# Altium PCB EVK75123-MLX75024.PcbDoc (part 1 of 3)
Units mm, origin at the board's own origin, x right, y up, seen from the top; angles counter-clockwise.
Board outline 80 x 50 mm, 8 copper layers (Top Layer, GND_T, Signal Layer 1, Vcc1, Vcc2, Signal Layer 2, GND_B, Bottom Layer), stack 1.548 mm thick; 222 components, 135 nets, 746 pads, 778 vias.
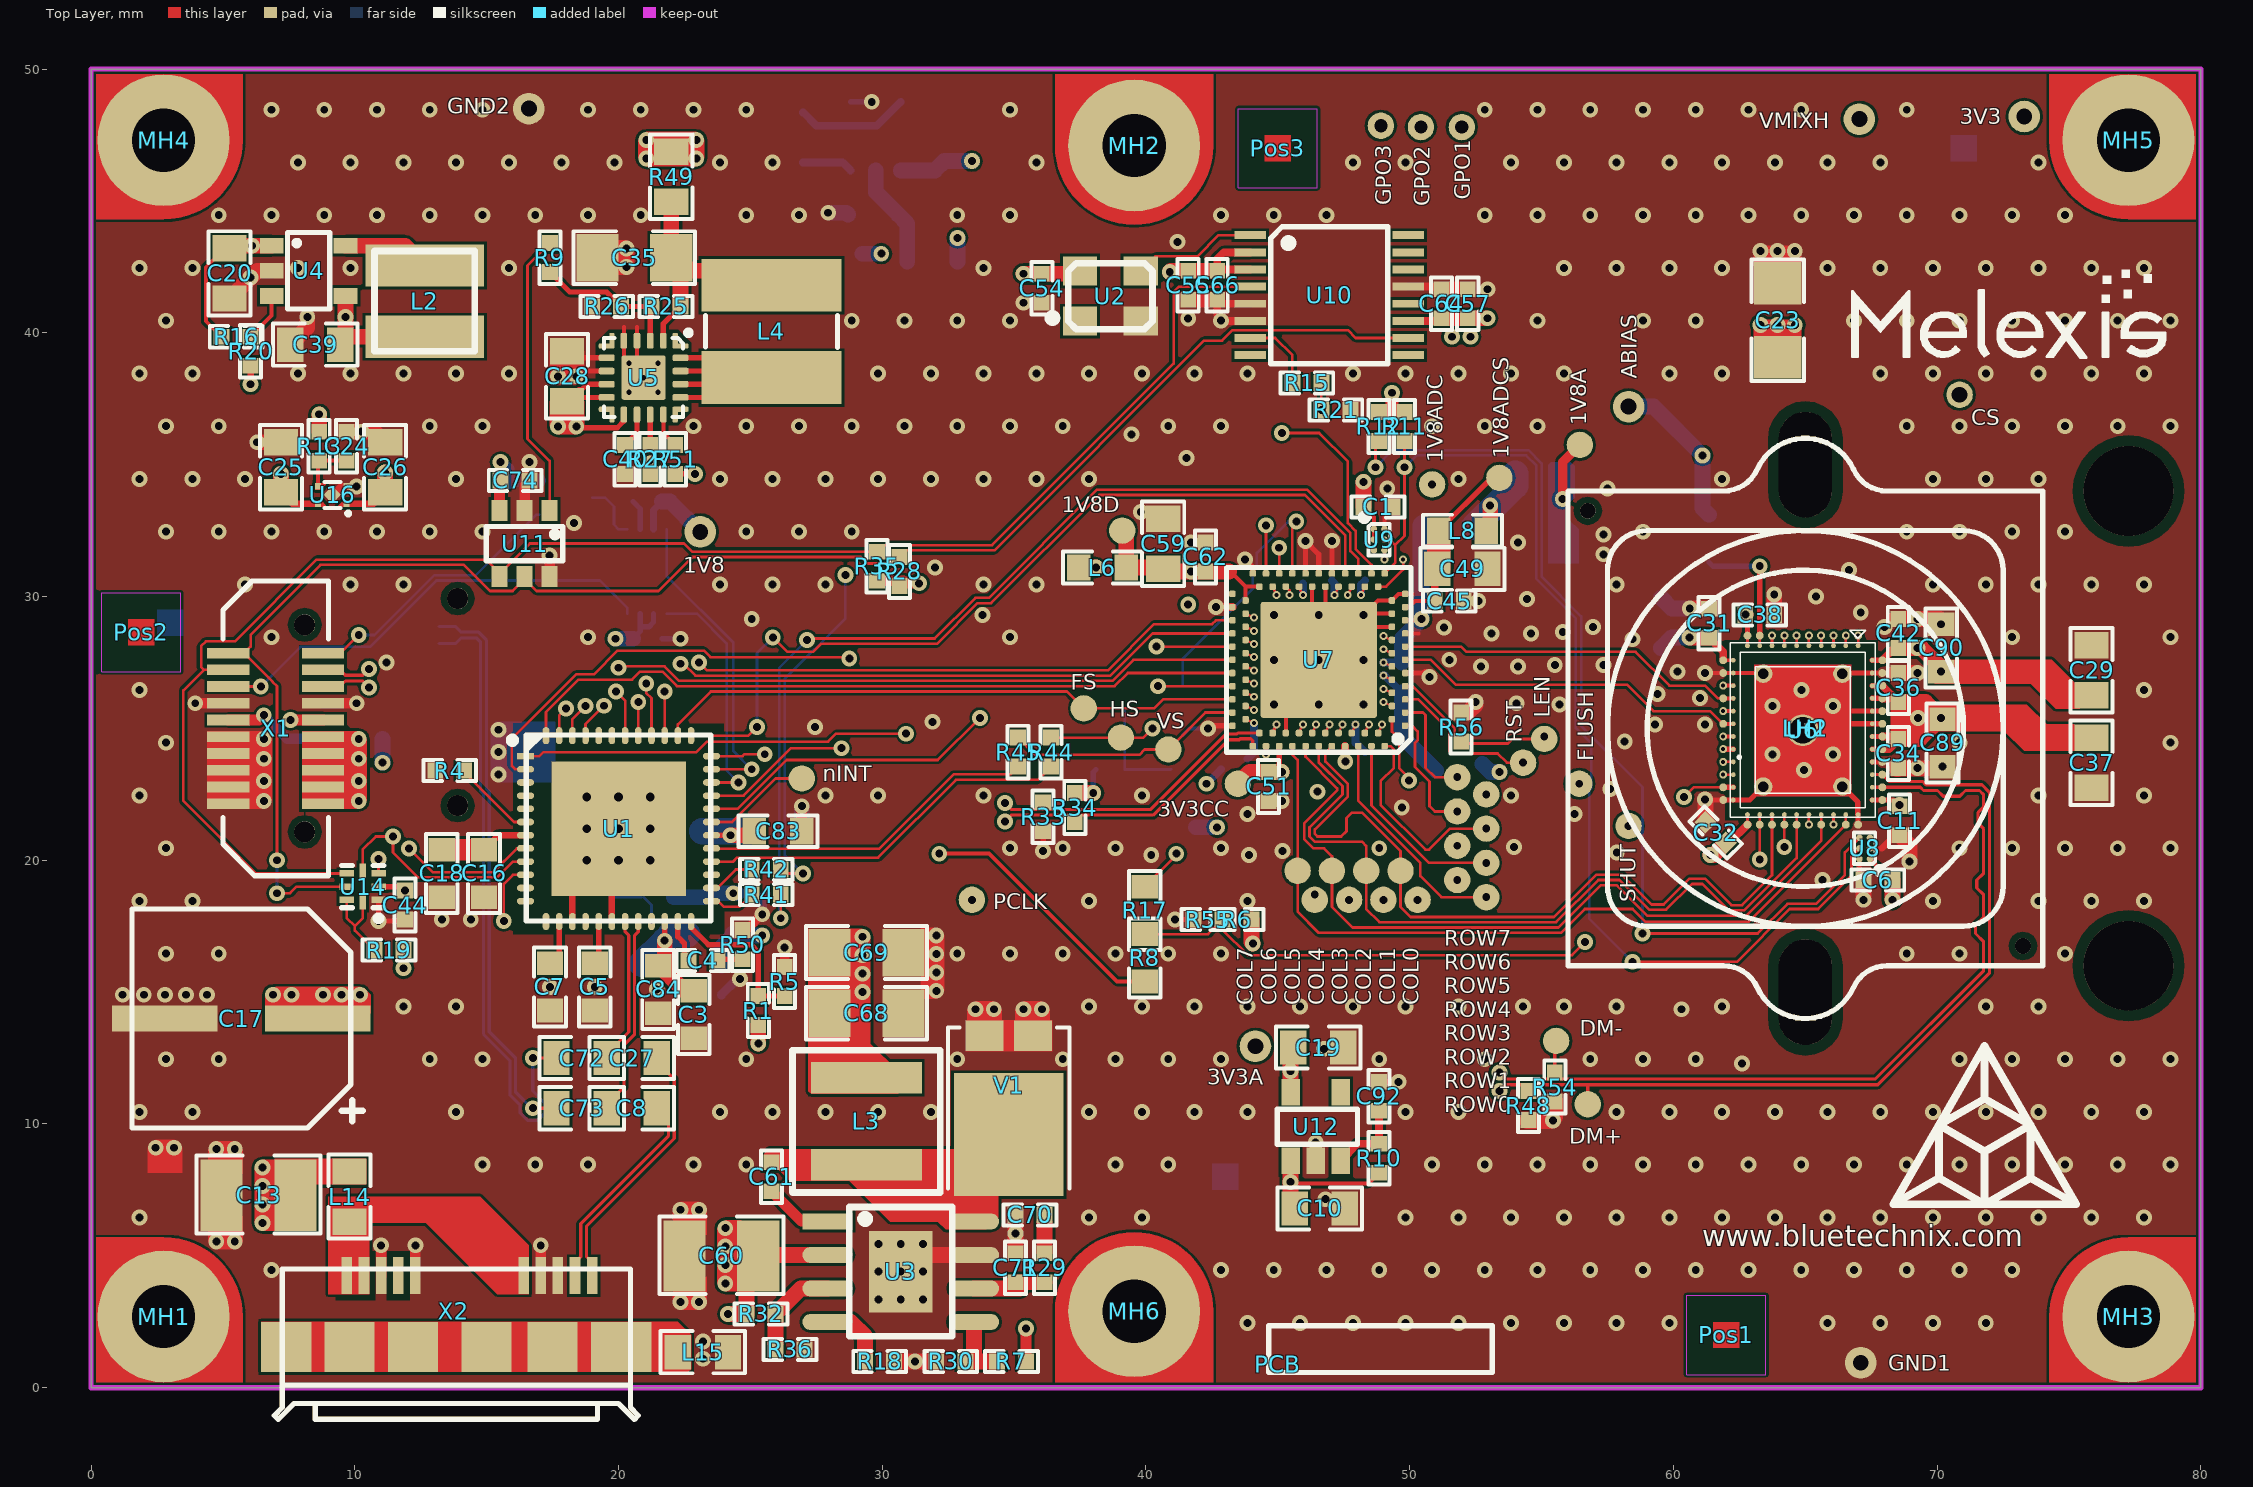
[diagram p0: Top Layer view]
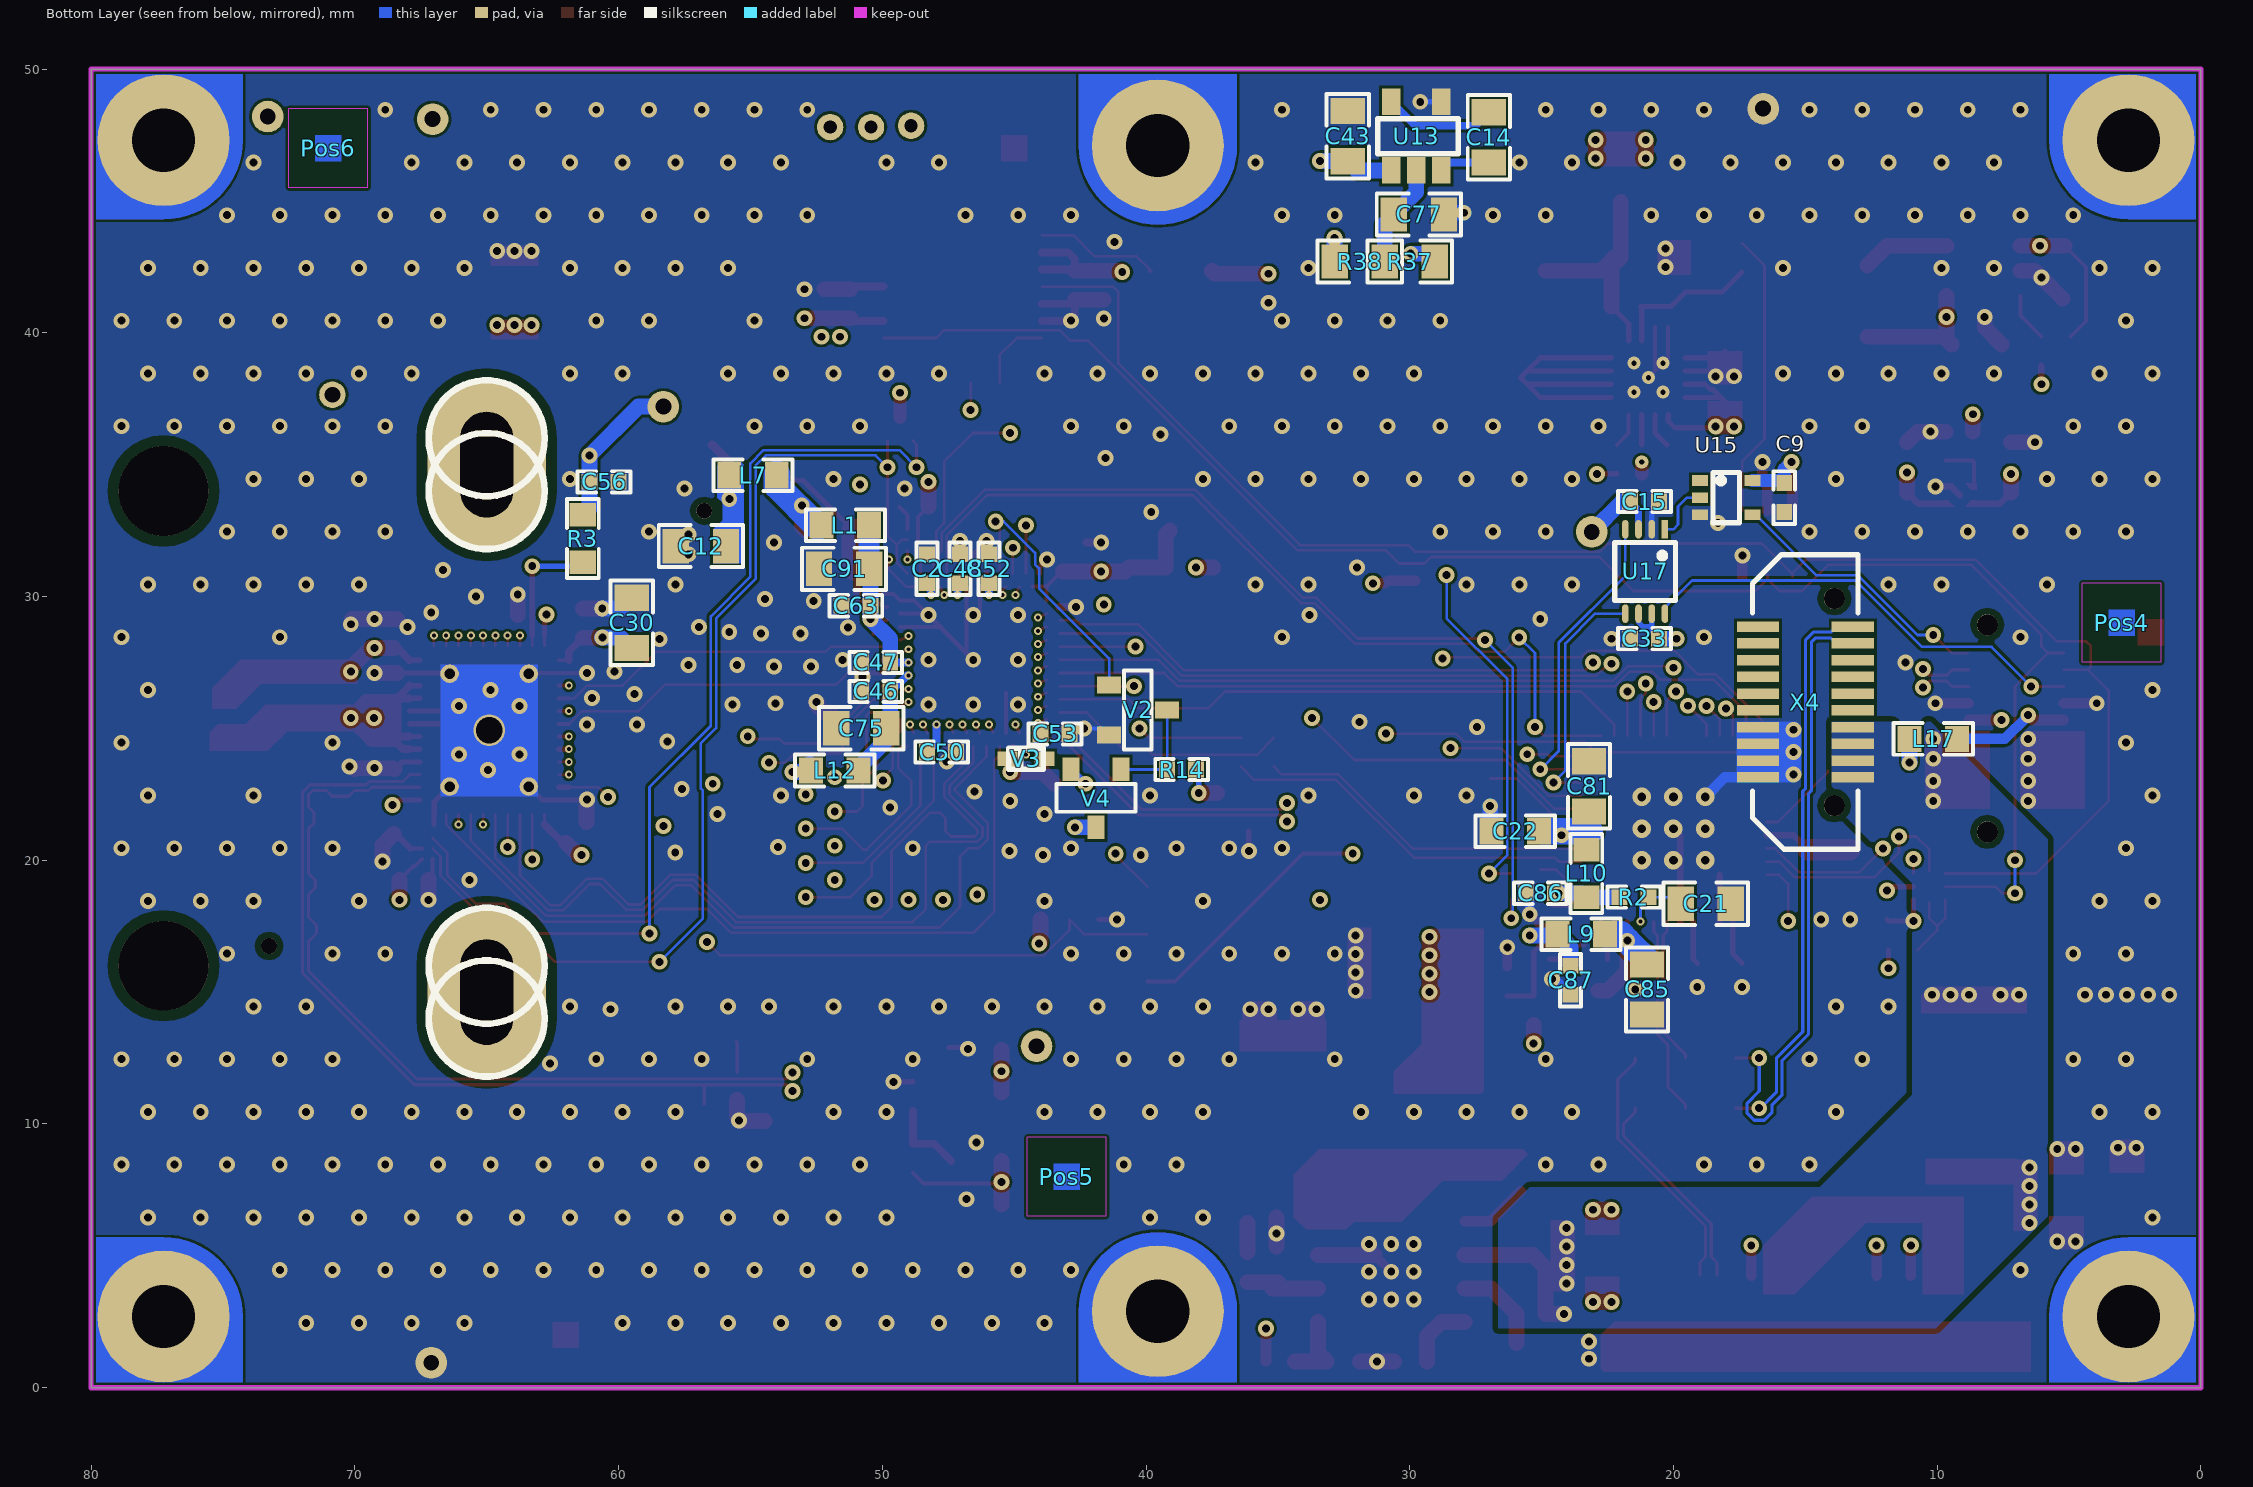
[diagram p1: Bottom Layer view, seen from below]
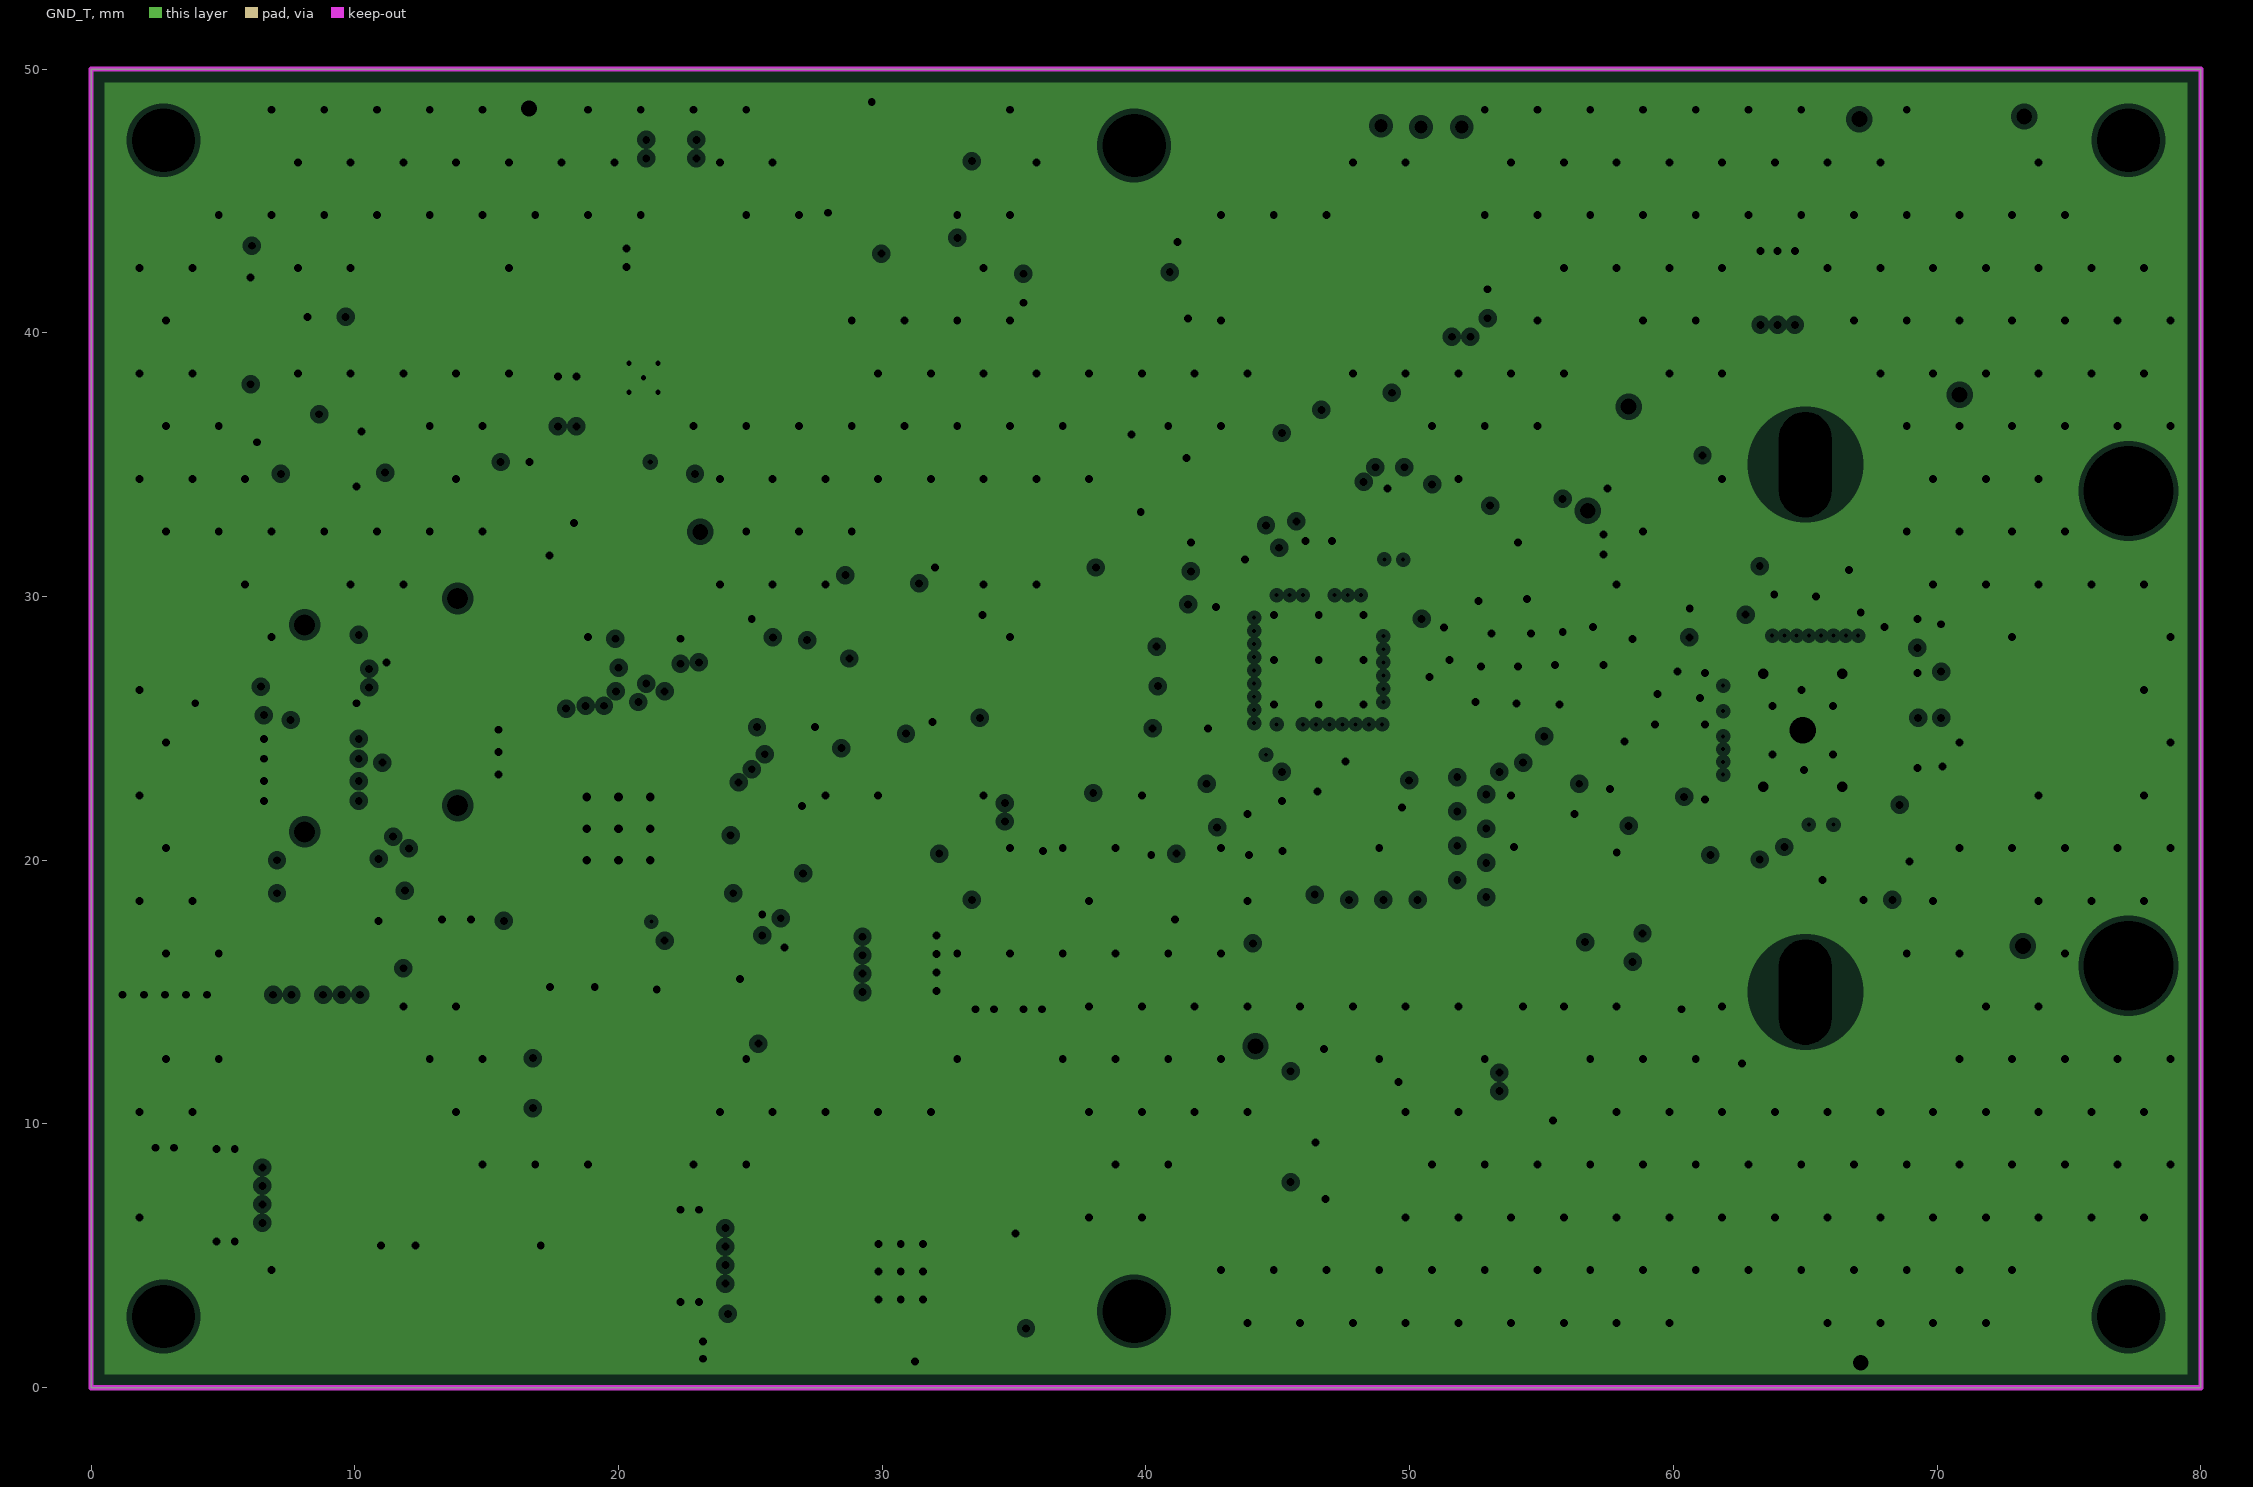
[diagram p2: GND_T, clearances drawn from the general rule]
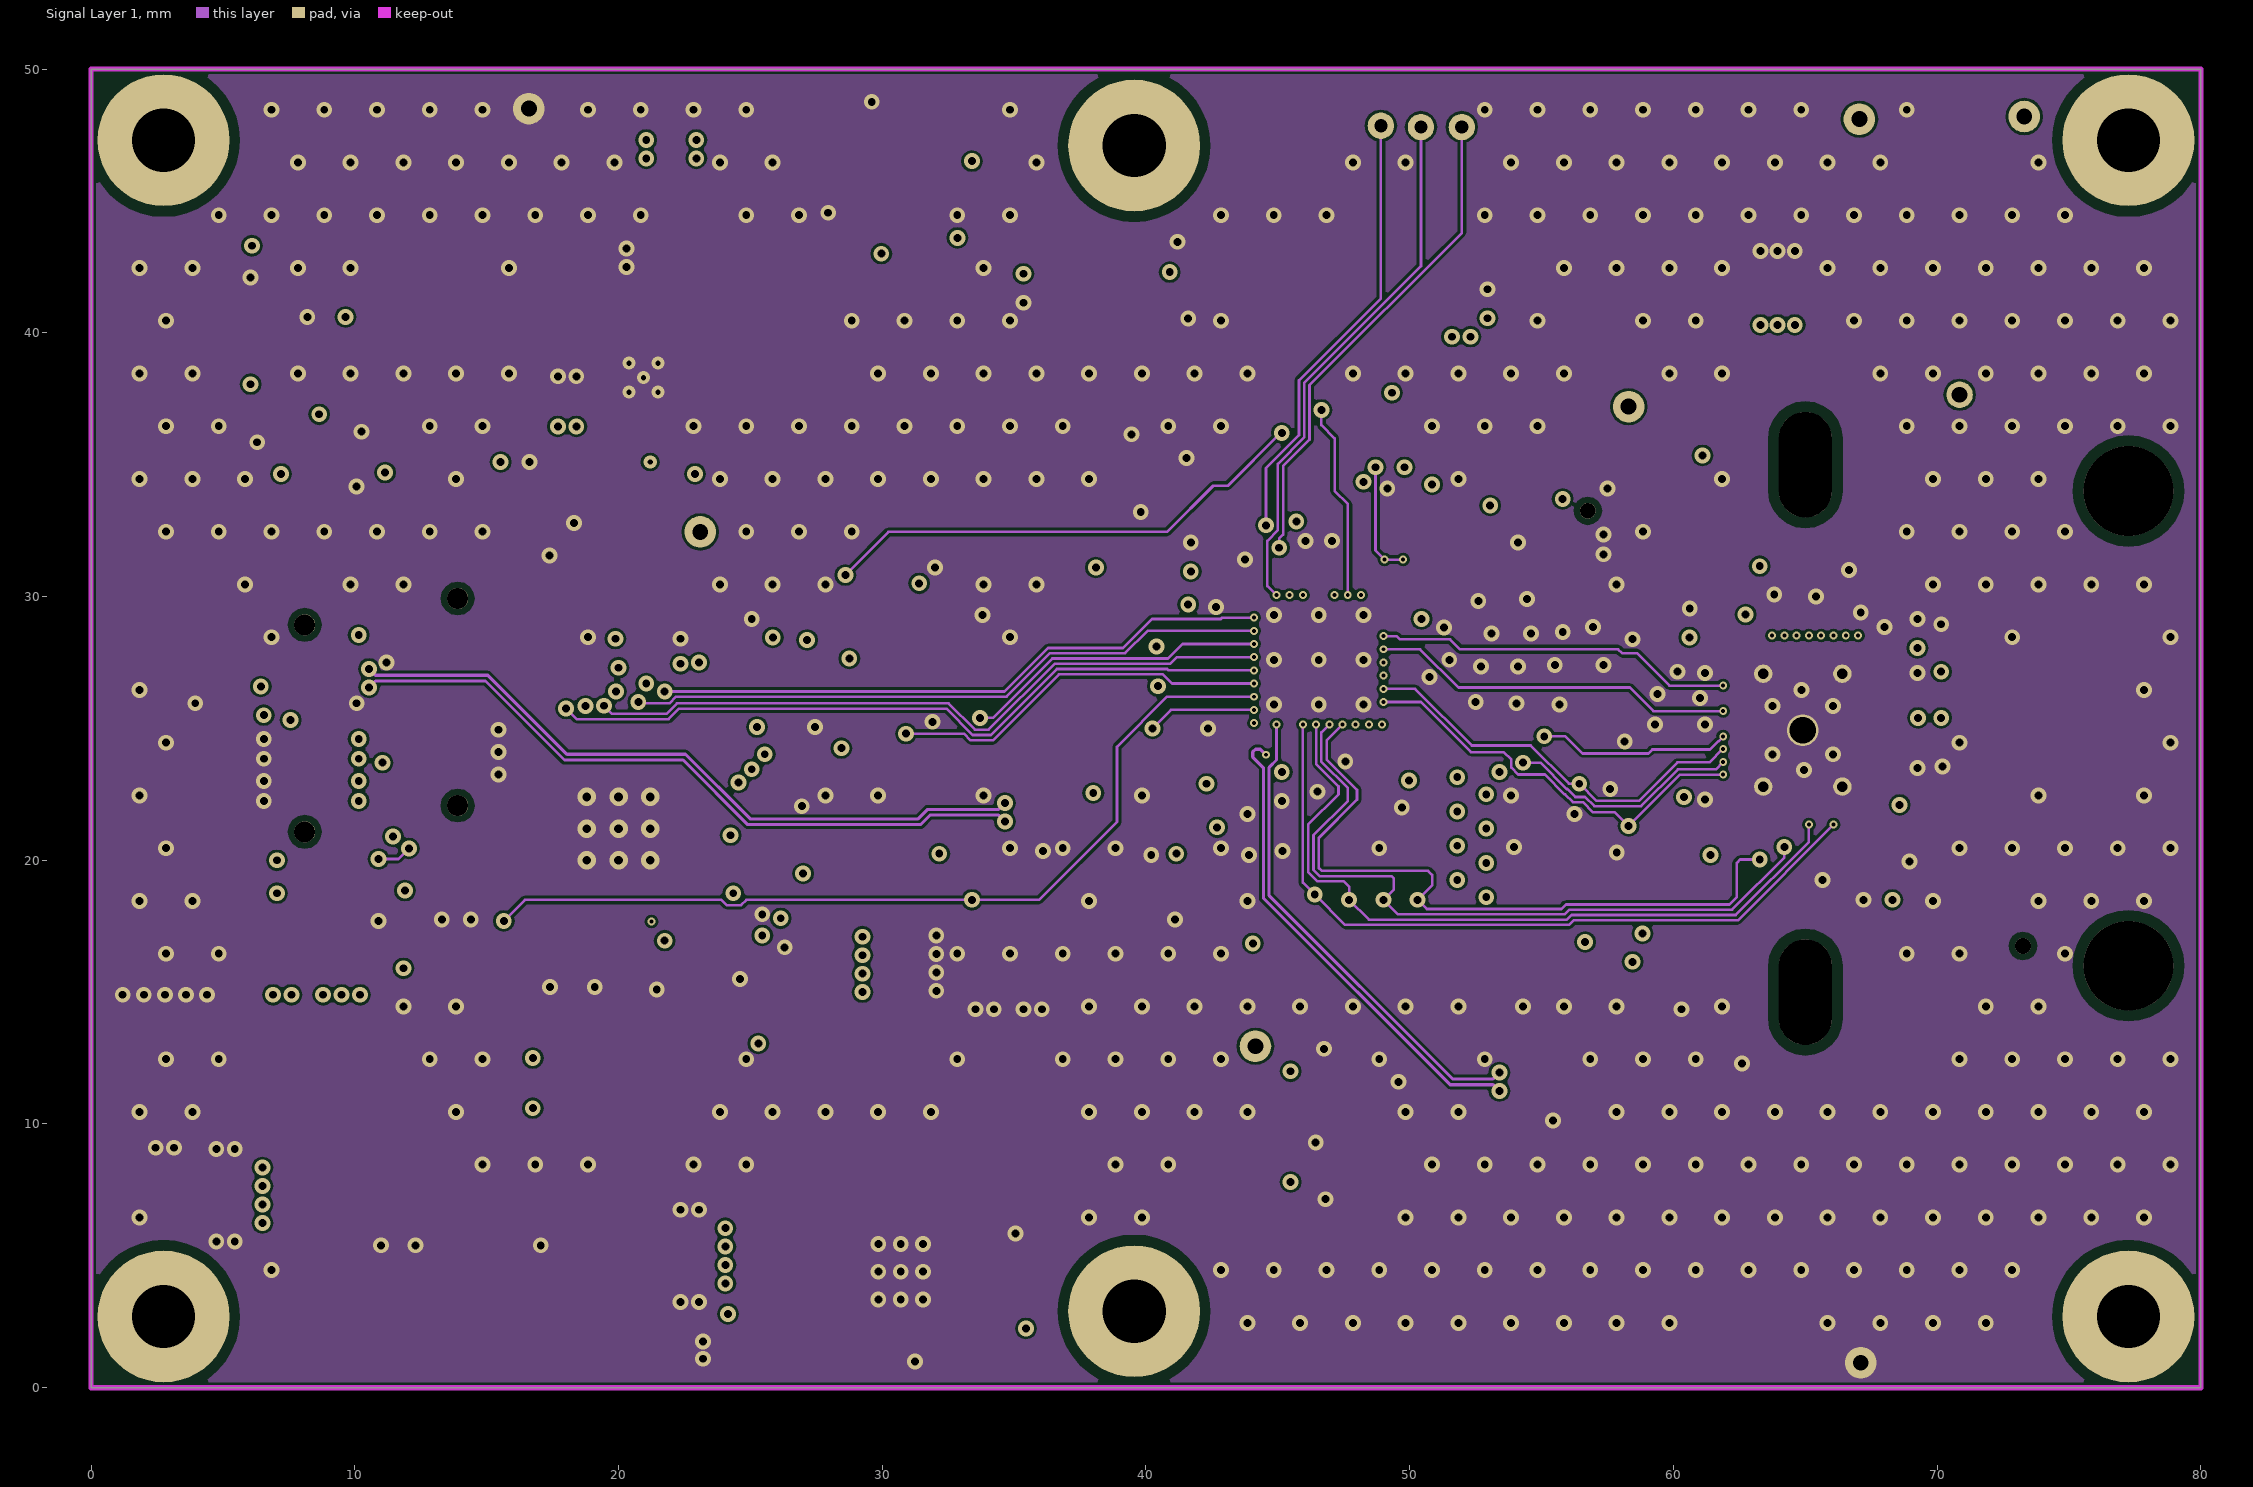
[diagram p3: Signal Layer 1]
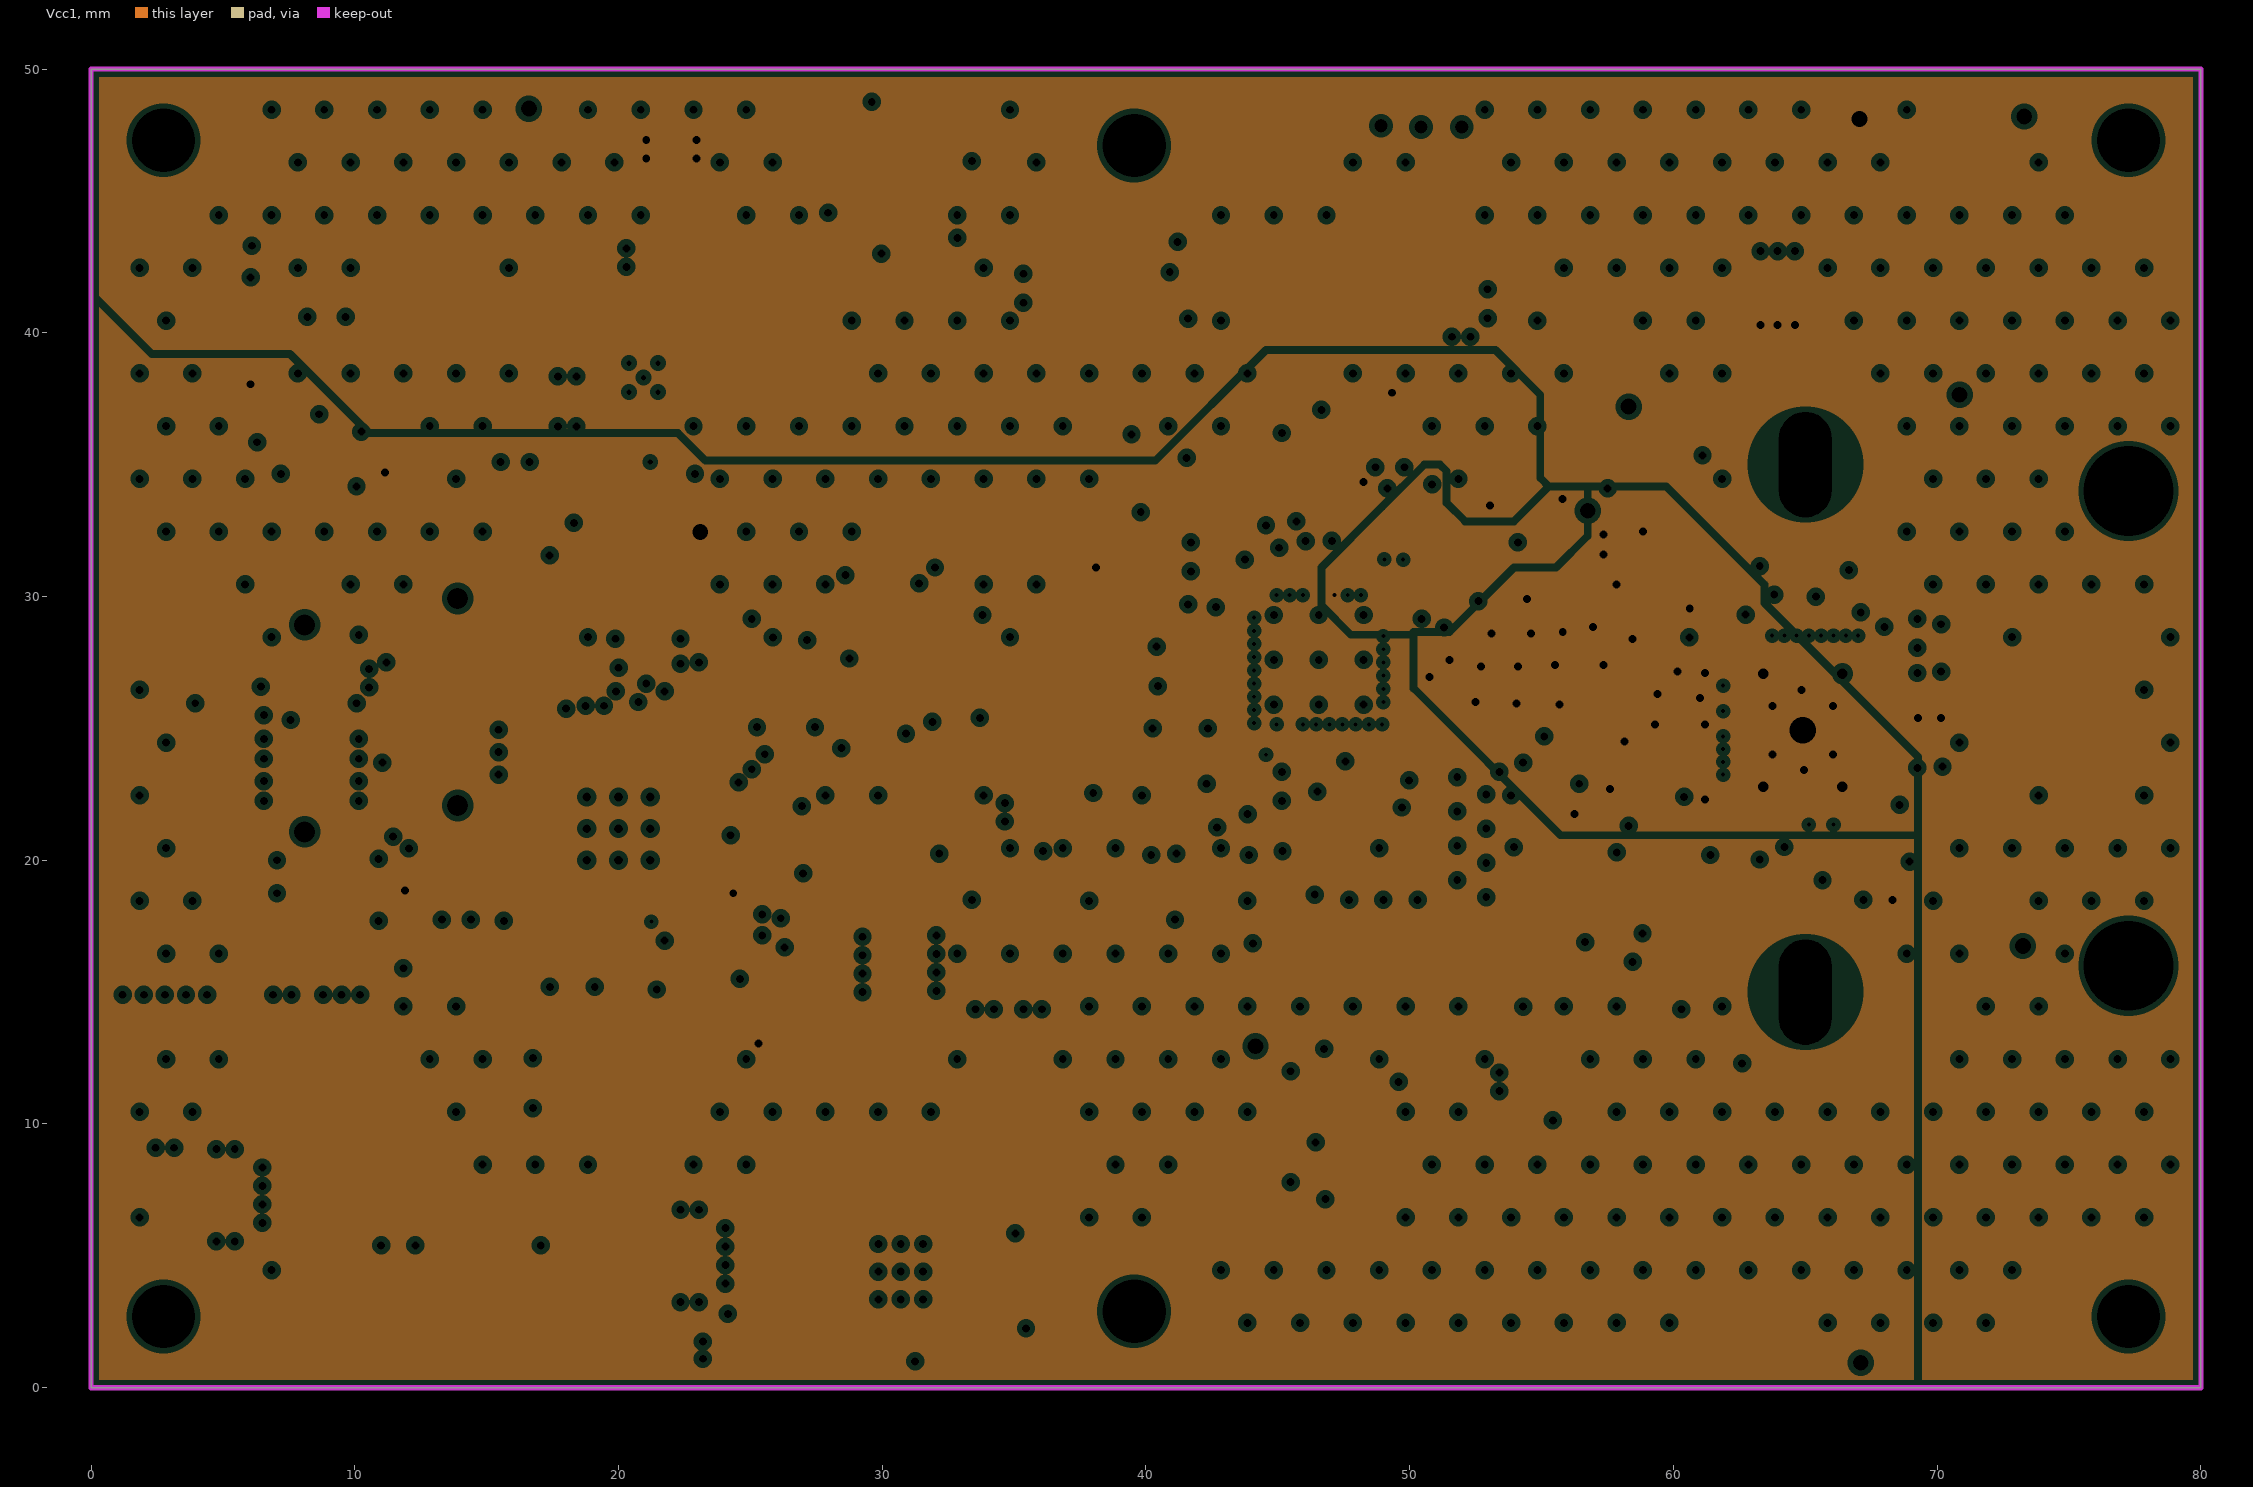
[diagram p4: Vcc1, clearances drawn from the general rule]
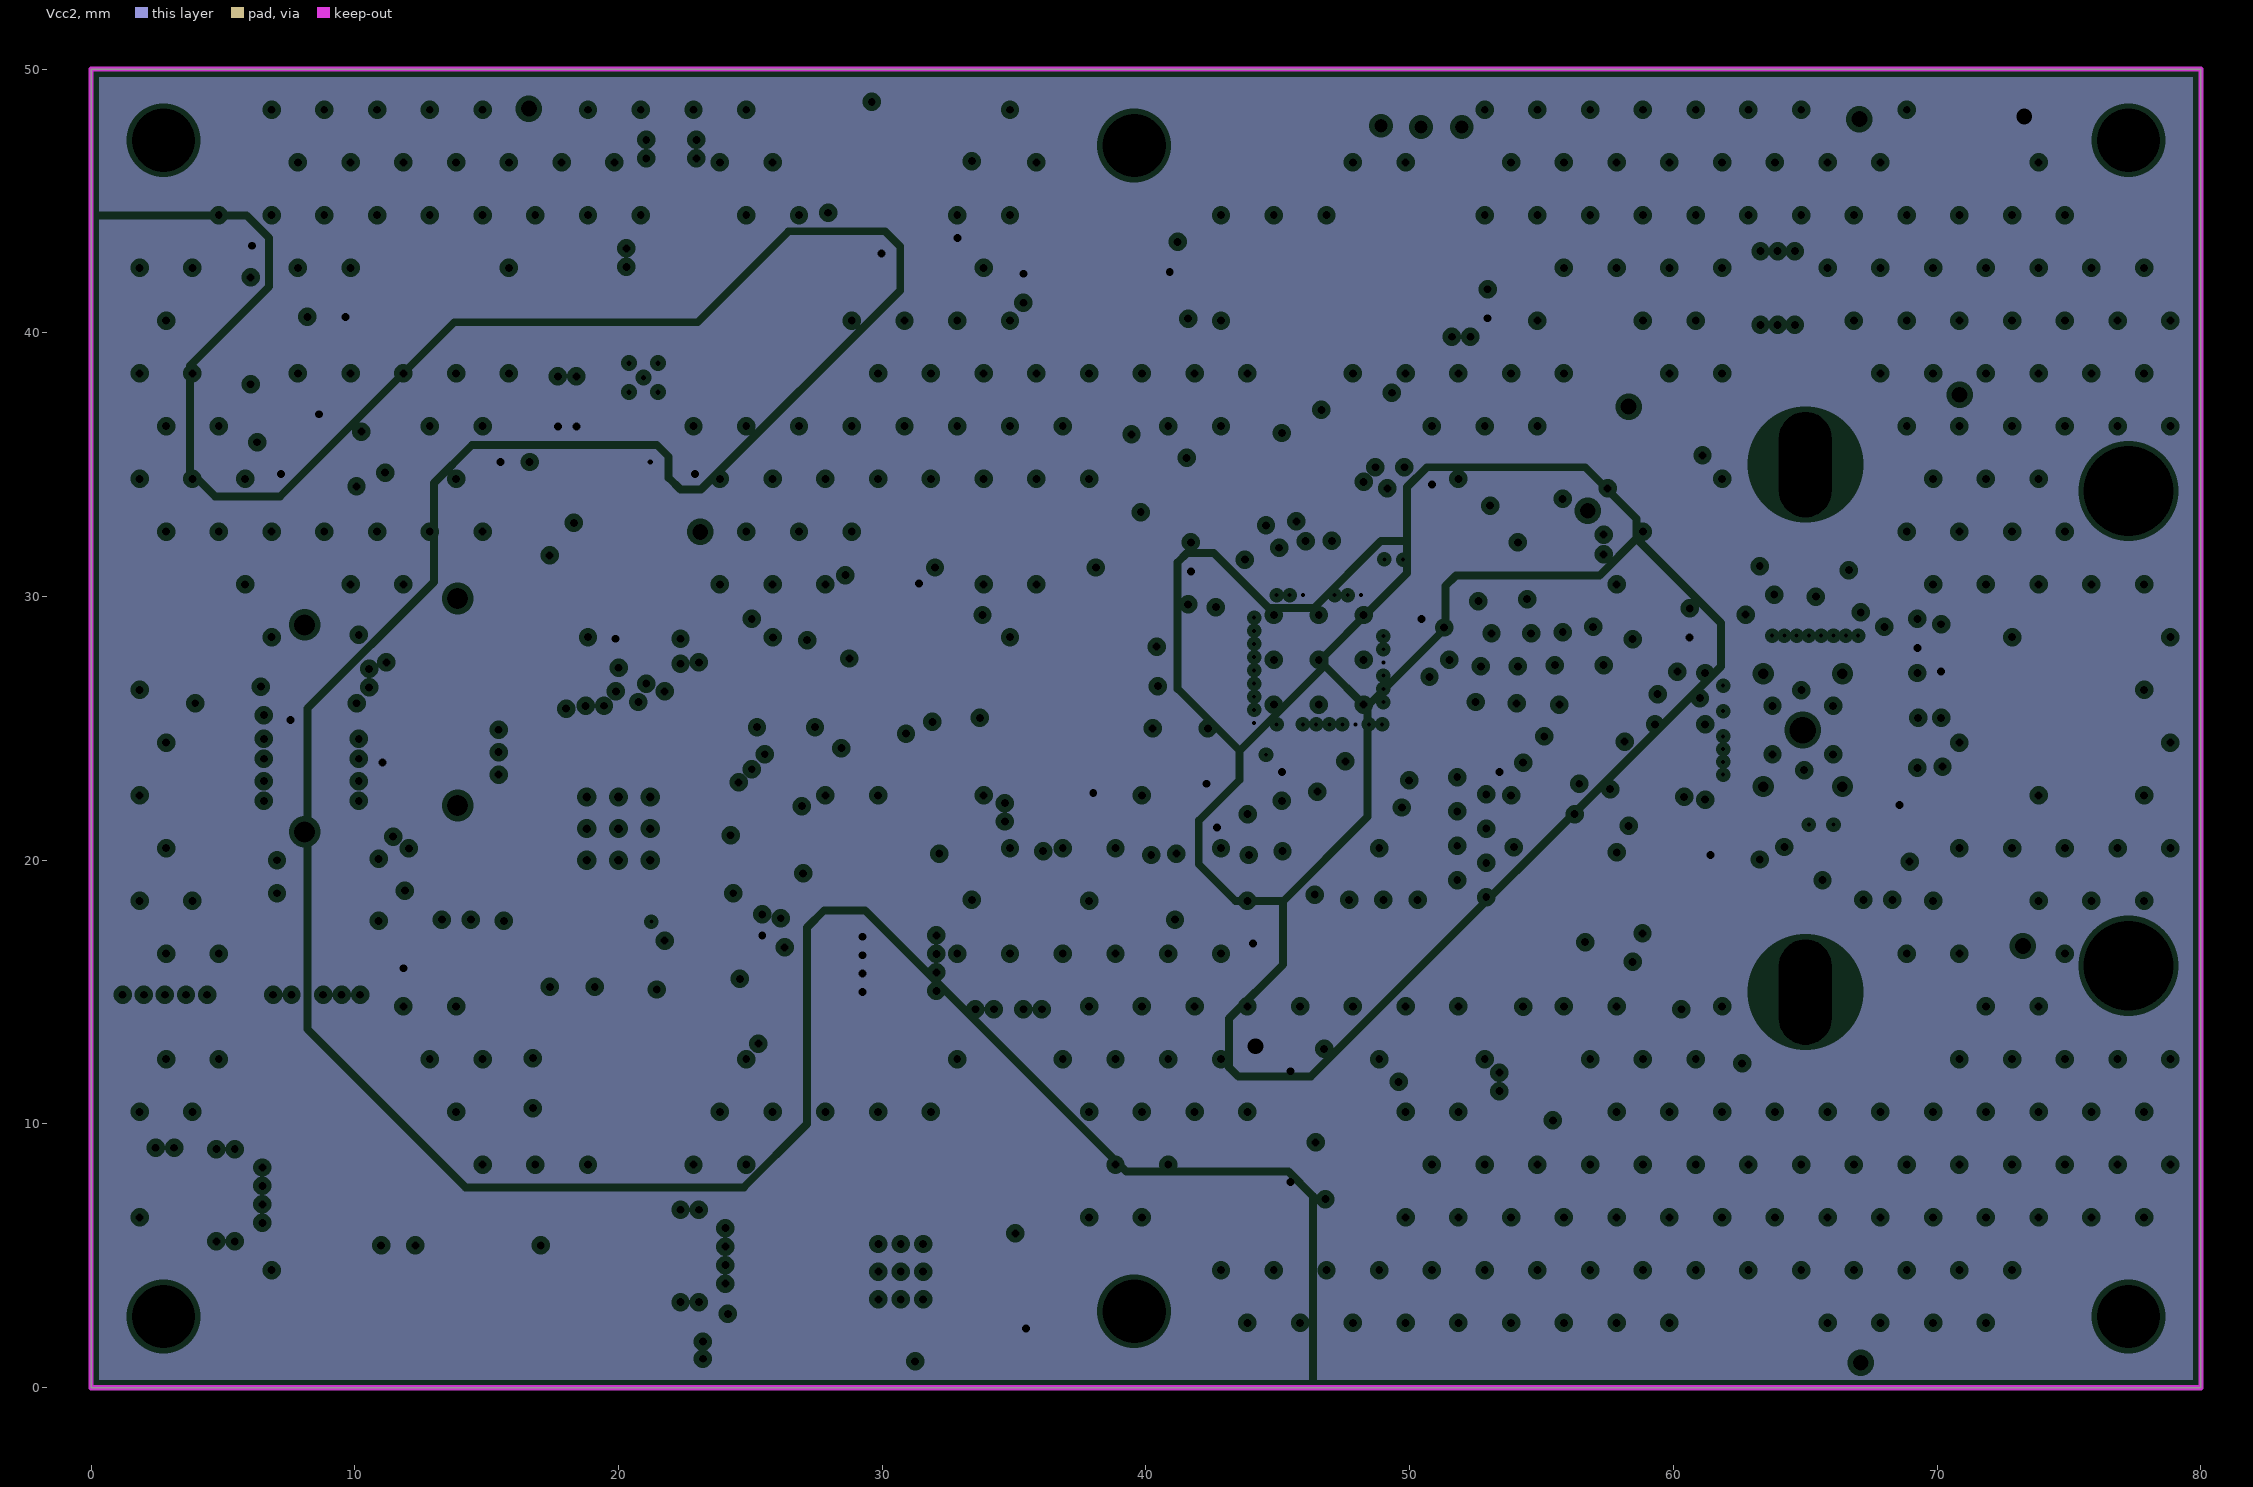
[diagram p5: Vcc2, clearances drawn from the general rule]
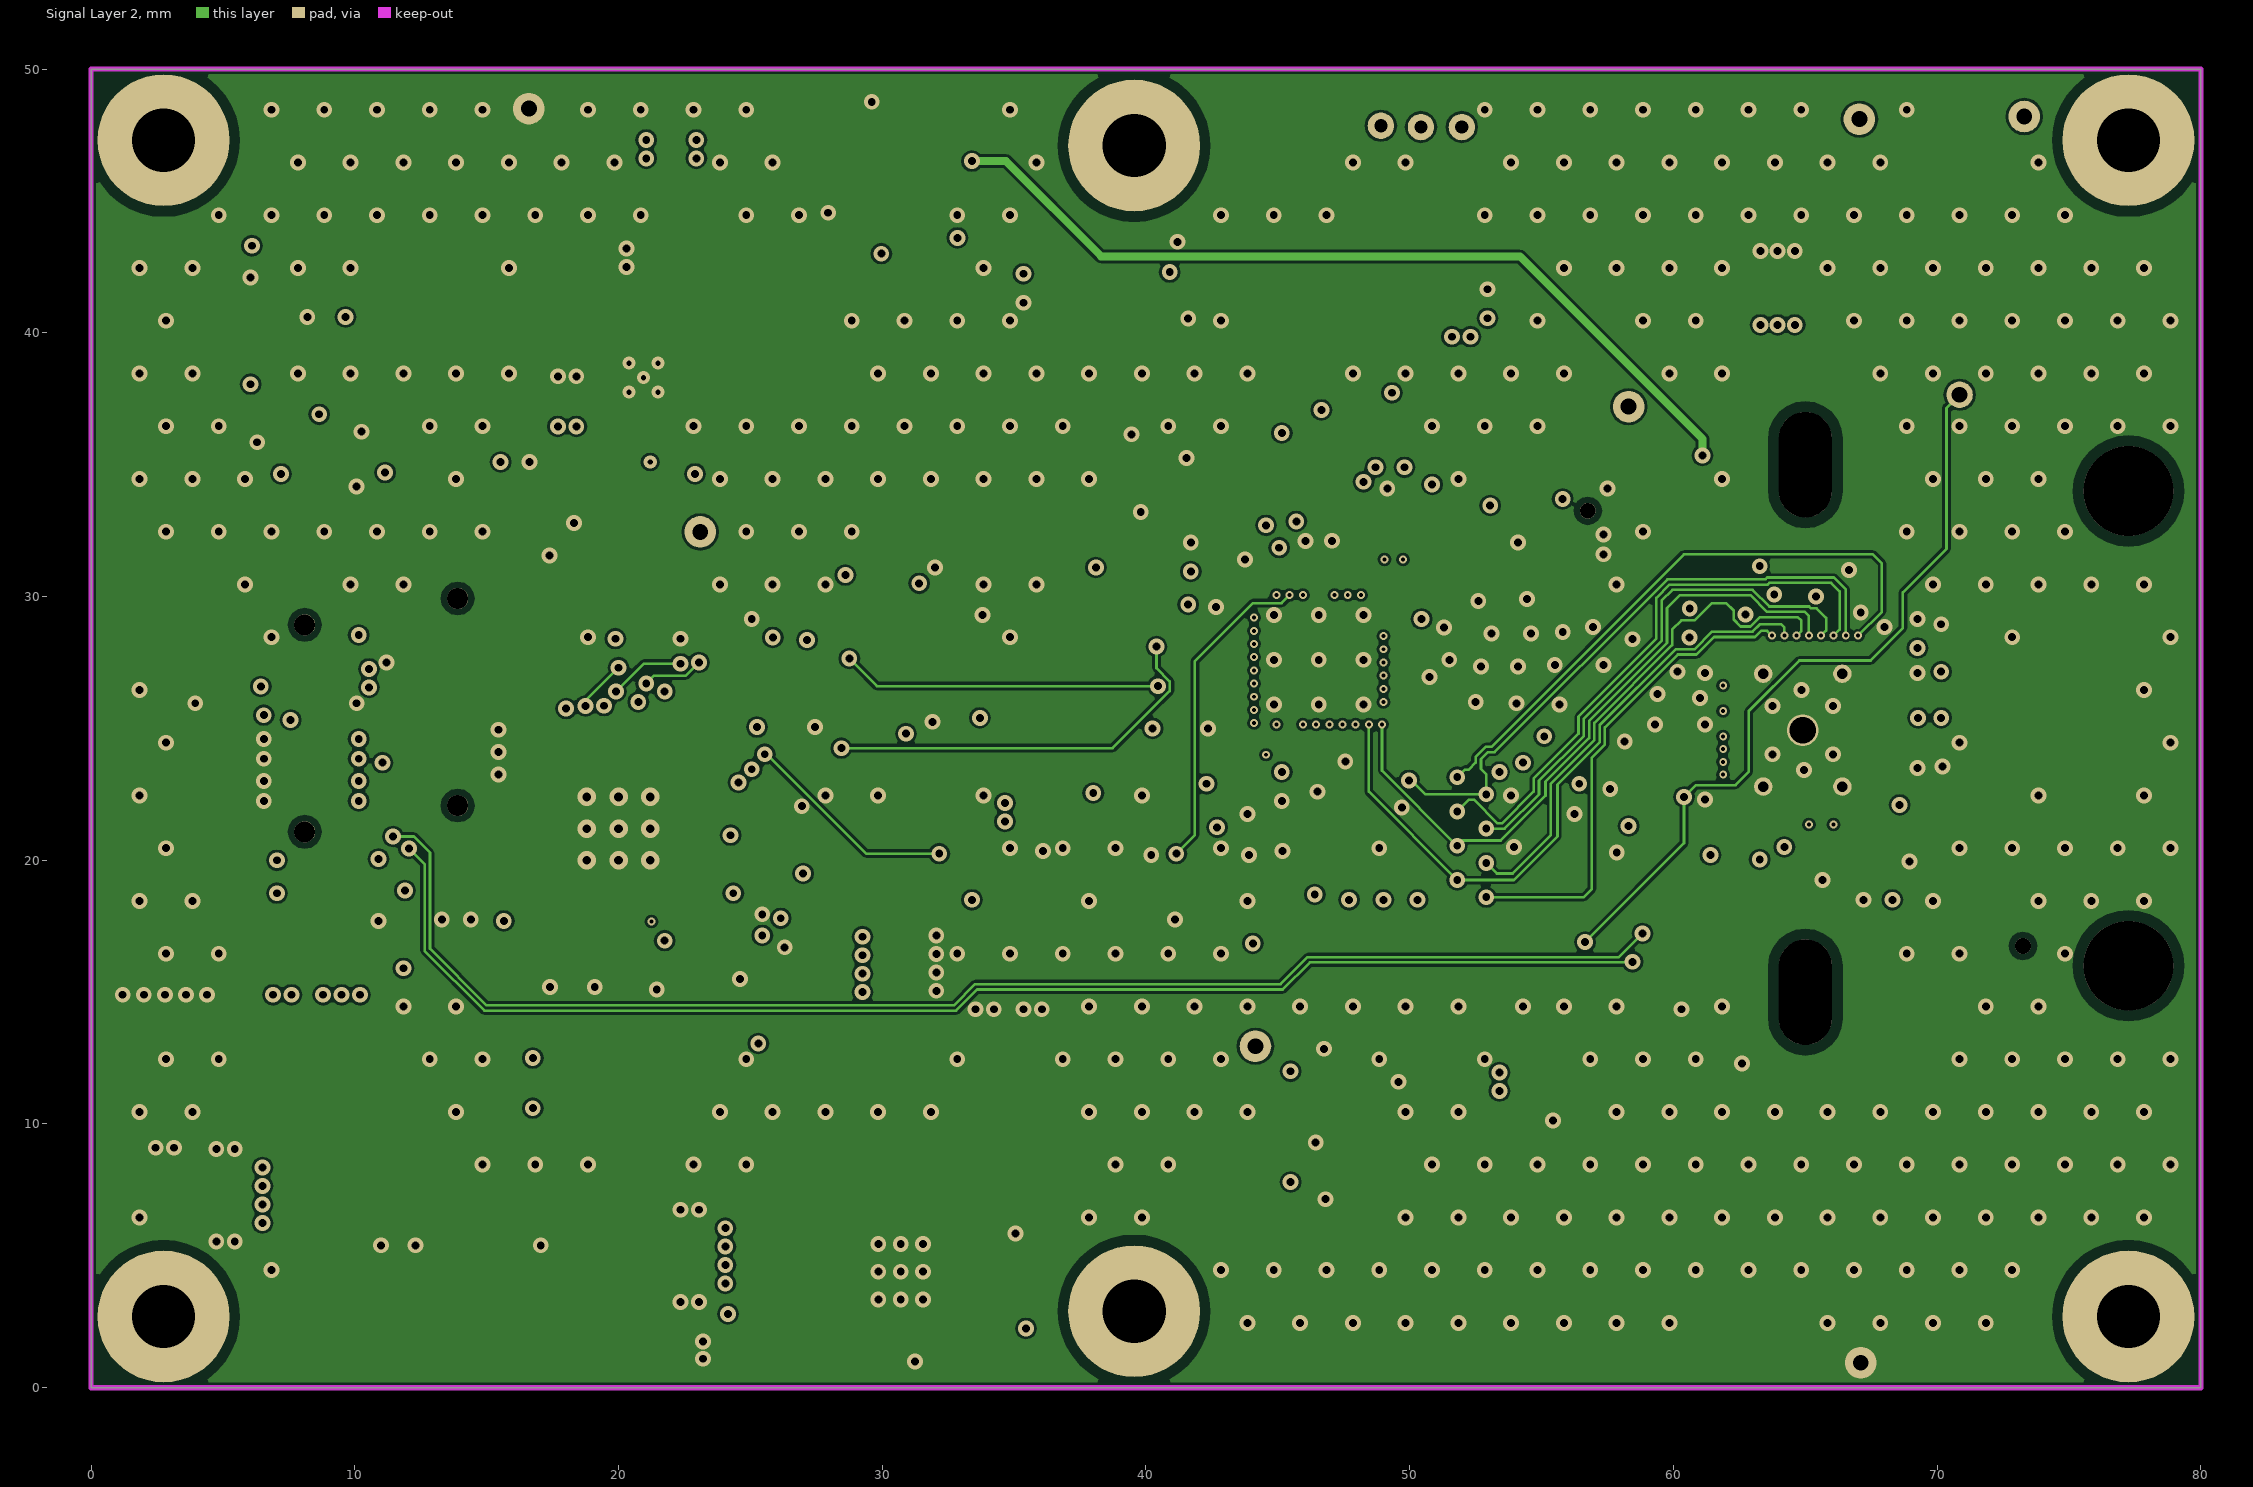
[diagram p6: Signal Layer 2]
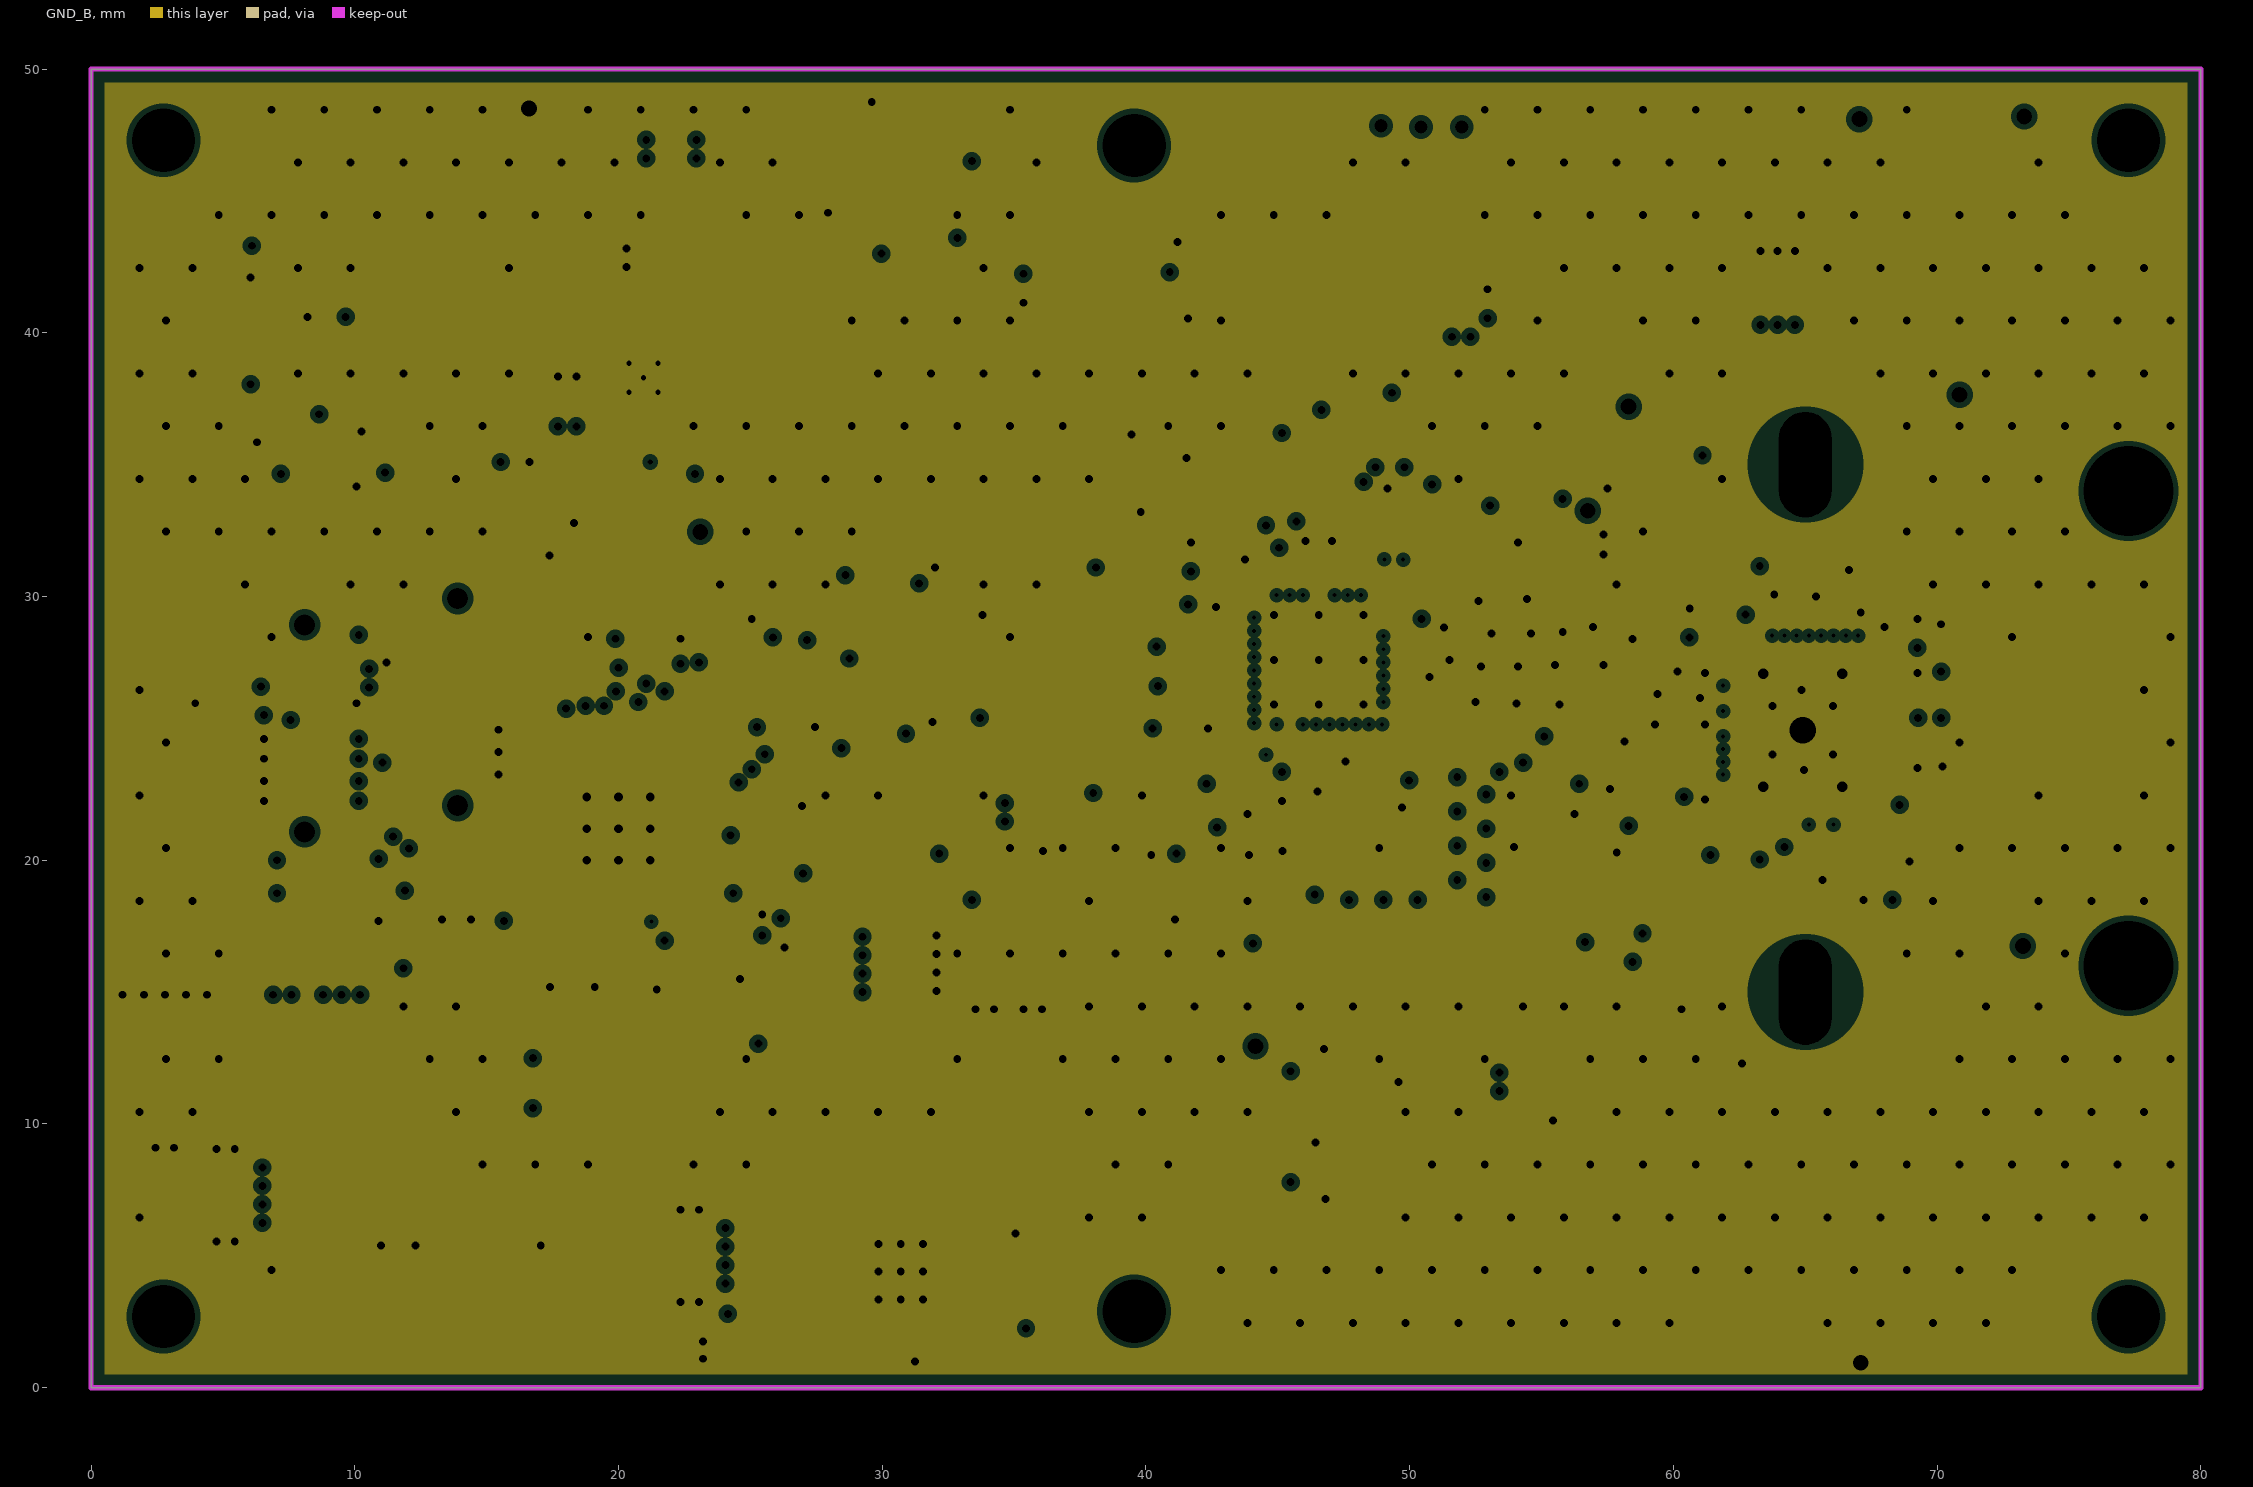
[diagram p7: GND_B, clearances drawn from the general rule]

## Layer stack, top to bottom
Top Solder: solder mask 0.024, Solder Resist, Dk 3.5
Top Layer: signal copper 0.039
Dielectric1: core 0.1, FR-4, Dk 4.2
GND_T: plane copper 0.036, net GND
Dielectric 7: prepreg 0.127, Dk 4.2
Signal Layer 1: signal copper 0.036
Dielectric2: core 0.3, FR-4, Dk 4.2
Vcc1: plane copper 0.036, net (Multiple Nets)
Dielectric 4: prepreg 0.2, Dk 4.2
Vcc2: plane copper 0.036, net (Multiple Nets)
Dielectric 5: core 0.3, Dk 4.2
Signal Layer 2: signal copper 0.036
Dielectric3: prepreg 0.127, FR-4, Dk 4.2
GND_B: plane copper 0.036, net GND
Dielectric 6: core 0.1, Dk 4.2
Bottom Layer: signal copper 0.039
Bottom Solder: solder mask 0.024, Solder Resist, Dk 3.5

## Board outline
0,0 80,0 80,50 0,50

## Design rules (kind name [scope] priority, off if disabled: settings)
AssemblyTestPointUsage [not (NetPinCount = 1)] p1: allowmultiple=TRUE
AssemblyTestpoint AssemblyTestpoint_Pad [(IsPad And (OnTopLayer)OR (OnBottom))] p1: testpointundercomponent=TRUE minsize=0.8 maxsize=3 preferedsize=0.8 minholesize=0 maxholesize=0 preferedholesize=0 testpointgrid=0.025 usegrid=FALSE gridtolerance=0 allowsidebottom=TRUE minspacing=2.54
AssemblyTestpoint AssemblyTestpoint_Via [(IsVia)] p2: testpointundercomponent=TRUE minsize=0.6 maxsize=0.8 preferedsize=0.8 minholesize=0 maxholesize=0.3 preferedholesize=0.3 testpointgrid=0.025 usegrid=FALSE gridtolerance=0 allowsidebottom=TRUE minspacing=2.54
AssemblyTestpoint AssemblyTestpoint_THT [(IsPad And OnMultiLayer)] p3: testpointundercomponent=TRUE minsize=0.5 maxsize=5 preferedsize=1.524 minholesize=0 maxholesize=3 preferedholesize=0.813 testpointgrid=0.025 usegrid=FALSE gridtolerance=0 allowsidetop=TRUE allowsidebottom=TRUE
AssemblyTestpoint [All] p4: testpointundercomponent=TRUE minsize=1.016 maxsize=2.54 preferedsize=1.524 minholesize=0 maxholesize=1.016 preferedholesize=0.813 testpointgrid=0.025 usegrid=TRUE gridtolerance=0 allowsidetop=TRUE allowsidebottom=TRUE
Clearance Clearance_MH [InPolygon vs InPadClass('MH')] p1: gap=0.4 ignorepadtopadclearanceinfootprint=FALSE
Clearance Clearance_Hole [All vs not PadIsPlated] p2: gap=0.23 ignorepadtopadclearanceinfootprint=FALSE except(0: Arc-Hole Track-Hole SMDPad-Hole THPad-Hole Via-Hole Fill-Hole Poly-Hole Region-Hole Text-Hole)
Clearance [All] p3: gap=0.1 ignorepadtopadclearanceinfootprint=FALSE except(0: Arc-Hole Track-Hole SMDPad-Hole THPad-Hole Via-Hole Fill-Hole Poly-Hole Region-Hole Text-Hole; 0.2: Poly-Poly)
ComponentClearance [All] p1: gap=0.01 collisioncheckmode=3 verticalgap=0.01 showdistances=FALSE
DiffPairsRouting DiffPair_100DiffPairsRouting [InNetClass('DIFF100')] p1: maxlimit=0.1 minlimit=0.1 mostfreqgap=0.1 toplayer_minwidth=0.12 toplayer_maxwidth=0.12 toplayer_prefwidth=0.12 midlayer1_minwidth=0.12 midlayer1_maxwidth=0.12 midlayer1_prefwidth=0.12 midlayer2_minwidth=0.12 midlayer2_maxwidth=0.12 midlayer2_prefwidth=0.12 bottomlayer_minwidth=0.12 bottomlayer_maxwidth=0.12 bottomlayer_prefwidth=0.12 maxuncoupledlength=2
DiffPairsRouting DiffPair_90DiffPairsRouting [InDifferentialPair ('D')] p2: maxlimit=0.12 minlimit=0.12 mostfreqgap=0.12 toplayer_minwidth=0.1 toplayer_maxwidth=0.1 toplayer_prefwidth=0.1 midlayer1_minwidth=0.1 midlayer1_maxwidth=0.1 midlayer1_prefwidth=0.1 midlayer2_minwidth=0.1 midlayer2_maxwidth=0.1 midlayer2_prefwidth=0.1 bottomlayer_minwidth=0.1 bottomlayer_maxwidth=0.1 bottomlayer_prefwidth=0.1 maxuncoupledlength=10
HoleSize [All] p1: absolutevalues=TRUE maxlimit=4 minlimit=0.1 maxpercent=80.000 minpercent=20.000
HoleToHoleClearance [All] p1: gap=0.15 allowstackedmicrovias=TRUE
MatchedLengths DiffPair_100MatchedLengths [InDifferentialPair ('DDR.CLK')] p1: tolerance=25.4 checknetsindiffpair=TRUE checkdiffpairvsdiffpair=FALSE checkxsignals=FALSE checkothers=FALSE
MinimumSolderMaskSliver [All vs IsVia] p1: minsoldermaskwidth=0.1
PlaneClearance PlaneClearance_MH [InPadClass('MH')] p1: clearance=0.5
PlaneClearance [All] p2: clearance=0.2
PlaneConnect [All] p1: planeconnectstyle=Direct reliefexpansion=0.5 reliefentries=4 reliefconductorwidth=0.3 reliefairgap=0.2
PolygonConnect [All] p1: connectstyle=Direct reliefconductorwidth=0.25 reliefentries=4 polygonreliefangle="90 Angle" airgapwidth=0.15
PolygonConnect PolygonConnect1 [InNet('GND')] p2: connectstyle=Direct reliefconductorwidth=0.2 reliefentries=4 polygonreliefangle="90 Angle" airgapwidth=0.254
RoutingVias [All] p1: holewidth=0.3 width=0.6 viastyle="Through Hole" minholewidth=0.1 minwidth=0.3 maxholewidth=1 maxwidth=1.3
SMDEntry [All] p1 off: side=TRUE corner=TRUE anyangle=FALSE
SilkToSolderMaskClearance SilkscreenOverComponentPads [IsPad] p1: minsilkscreentomaskgap=0.254 clearancetoexposedcopper=TRUE
SolderMaskExpansion SolderMaskExpansion_Via [IsVia] p1: expansion=-0.075
SolderMaskExpansion SolderMaskExpansion_ALL [All] p2: expansion=0.05
UnConnectedPin [All] p1:
ViasUnderSMD [All] p1: allowed=TRUE
Width [All] p1: maxlimit=3 minlimit=0.1 preferedwidth=0.15 checkconnectedcopper=TRUE
20 further rules are at their usual default settings.

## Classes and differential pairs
net class I2CH: I2CH.SCL I2CH.SDA
net class I2CL: I2CL.SCL I2CL.SDA
net class CSI: CSI.D0 CSI.D1 CSI.D2 CSI.D3 CSI.D4 CSI.D5 CSI.D6 CSI.D7 CSI.D8 CSI.D9 CSI.D10 CSI.D11 CSI.FSYNC CSI.HSYNC CSI.nRESET CSI.PCLK CSI.QUIET CSI.TRIGGER CSI.VSYNC
net class CSI.D[11..0]: CSI.D0 CSI.D1 CSI.D2 CSI.D3 CSI.D4 CSI.D5 CSI.D6 CSI.D7 CSI.D8 CSI.D9 CSI.D10 CSI.D11
pad class EP: U1-0 U3-0 U4-0 U5-0 U6-0 U7-0
net class <Hi-Speed>: CCCLK D_B2B_N D_B2B_P D_USB_N D_USB_P DOUT_N DOUT_P LCLK1 LED.MOD_N LED.MOD_P LVDS_N LVDS_P MLX.DMIX_N MLX.DMIX_P
net class DIFF100: D_B2B_N D_B2B_P D_USB_N D_USB_P DOUT_N DOUT_P LED.MOD_N LED.MOD_P MLX.DMIX_N MLX.DMIX_P
component class U_Power: 1V8 3V3 3V3A C10 C14 C19 C20 C24 C25 C26 C28 C35 C39 C40 C43 C60 C61 C68 C69 C70 C71 C74 C77 C92 GND1 GND2 JP1 JP2 L2 L3 L4 P11 P12 R7 R9 R10 R13 R16 R18 R20 R25 R26 R27 R29 R30 R32 R36 R37 R38 R49 R51 U3 U4 U5 U11 U12 U13 U16 V1 VMIXH
component class TopLayer: MH1 MH2 MH3 MH4 MH5 MH6 PCB Pos1 Pos2 Pos3 Pos4 Pos5 Pos6
component class U_Interfaces: C1 C3 C4 C5 C6 C7 C8 C9 C13 C15 C16 C17 C18 C21 C22 C27 C33 C44 C54 C55 C57 C64 C66 C72 C73 C81 C83 C84 C85 C86 C87 HS L9 L10 L14 L15 L17 nINT PCLK R1 R2 R4 R5 R11 R12 R15 R19 R21 R28 R33 R34 R35 R41 R42 R44 R45 R50 U1 U2 U8 U9 U10 U14 U15 U17 VS X1 X2 X4
component class U_ToF-Sensor: 1V8A 1V8ADC 1V8ADCS 1V8D 3V3CC ABIAS AN4 C2 C11 C12 C23 C29 C30 C31 C32 C34 C36 C37 C38 C42 C45 C46 C47 C48 C49 C50 C51 C52 C53 C56 C59 C62 C63 C75 C89 C90 C91 COL0 COL1 COL2 COL3 COL4 COL5 COL6 COL7 CS DM+ DM- FLUSH FS GPO1 GPO2 GPO3 L1 L6 L7 L8 L12 LEN LH1 LH2 R3 R6 R8 R14 R17 R48 R54 R55 R56 ROW0 ROW1 ROW2 ROW3 ROW4 ROW5 ROW6 ROW7 RST SHUT U6 U7 V2 V3 V4
net class <Power>: 1V8 1V8A 1V8ADC 1V8ADCS 1V8D 3V3 3V3A 3V3CC 5V0 24V ABIAS GND VMIX
net class MLX.COL[7..0]: MLX.COL0 MLX.COL1 MLX.COL2 MLX.COL3 MLX.COL4 MLX.COL5 MLX.COL6 MLX.COL7
net class MLX.ROW[7..0]: MLX.ROW0 MLX.ROW1 MLX.ROW2 MLX.ROW3 MLX.ROW4 MLX.ROW5 MLX.ROW6 MLX.ROW7
net class MLX: MLX.COL0 MLX.COL1 MLX.COL2 MLX.COL3 MLX.COL4 MLX.COL5 MLX.COL6 MLX.COL7 MLX.CS MLX.DMIX_N MLX.DMIX_P MLX.L_EN MLX.PFLUSH MLX.ROW0 MLX.ROW1 MLX.ROW2 MLX.ROW3 MLX.ROW4 MLX.ROW5 MLX.ROW6 MLX.ROW7 MLX.RST MLX.SHUT
net class OUT[3..0]: OUT0 OUT1 OUT2 OUT3
pad class MH: Free-H1 Free-H2 LH1-4 LH1-8 MH1-1 MH2-1 MH3-1 MH4-1 MH5-1 MH6-1
differential pair D_USB: +D_USB_P -D_USB_N
differential pair D_B2B: +D_B2B_P -D_B2B_N
differential pair DOUT: +DOUT_P -DOUT_N
differential pair LED.MOD: +LED.MOD_P -LED.MOD_N
differential pair MLX.DMIX: +MLX.DMIX_P -MLX.DMIX_N

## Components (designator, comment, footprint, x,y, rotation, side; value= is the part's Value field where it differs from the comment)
1V8 "Test Pad" PAD_1.27mm_HMD 23.1,32.45 r0 top
1V8A "Test Pad" PAD_1mm_SMD#1 56.45,35.75 r0 top
1V8ADC "Test Pad" PAD_1mm_SMD#1 50.85,34.25 r90 top
1V8ADCS "Test Pad" PAD_1mm_SMD#1 53.4,34.5 r90 top
1V8D "Test Pad" PAD_1mm_SMD#1 39.1,32.5 r0 top
3V3 "Test Pad" PAD_1.27mm_HMD 73.3,48.2 r0 top
3V3A "Test Pad" PAD_1.27mm_HMD 44.15,12.95 r0 top
3V3CC "Test Pad" PAD_1mm_SMD#1 43.482,22.9 r90 top
ABIAS "Test Pad" PAD_1.27mm_HMD 58.3,37.2 r0 top
C1 "Capacitor non-polarized" 0402 48.8,33.4 r180 top
C2 "Capacitor non-polarized" 0402 48.3,31.05 r90 bottom
C3 "Capacitor non-polarized" 0603 22.85,14.15 r270 top
C4 "Capacitor non-polarized" 0402 23.2,16.2 r180 top
C5 "Capacitor non-polarized" 0603 19.1,15.2 r90 top
C6 "Capacitor non-polarized" 0402 67.75,19.25 r0 top
C7 "Capacitor non-polarized" 0603 17.4,15.2 r90 top
C8 "Capacitor non-polarized" 0805 20.5,10.6 r0 top
C9 "Capacitor non-polarized" 0402 15.8,33.75 r270 bottom
C10 "Capacitor non-polarized" 0805 46.583,6.8 r180 top
C11 "Capacitor non-polarized" 0402 68.575,21.5 r90 top
C12 "Capacitor non-polarized" 0805 56.875,31.911 r180 bottom
C13 "Capacitor non-polarized" 1210 6.35,7.3 r0 top
C14 "Capacitor non-polarized" 0805 27,47.408 r90 bottom
C15 "Capacitor non-polarized" 0402 21.1,33.6 r180 bottom
C16 "Capacitor non-polarized" 0603 14.9,19.5 r90 top
C17 "Polarized Capicator" ELKO_SMD-8x7 5.7,14 r0 top
C18 "Capacitor non-polarized" 0603 13.3,19.5 r90 top
C19 "Capacitor non-polarized" 0805 46.533,12.9 r180 top
C20 "Capacitor non-polarized" 0805 5.25,42.25 r90 top
C21 "Capacitor non-polarized" 0805 18.775,18.35 r0 bottom
C22 "Capacitor non-polarized" 0603 26,21.1 r0 bottom
C23 "Capacitor non-polarized" 1206 63.95,40.475 r270 top
C24 "Capacitor non-polarized" 0402 9.69,35.7 r90 top
C25 "Capacitor non-polarized" 0805 7.2,34.9 r270 top
C26 "Capacitor non-polarized" 0805 11.15,34.9 r270 top
C27 "Capacitor non-polarized" 0805 20.5,12.5 r0 top
C28 "Capacitor non-polarized" 0805 18.05,38.35 r270 top
C29 "Capacitor non-polarized" 0805 75.85,27.2 r270 top
C30 "Capacitor non-polarized" 0805 59.5,29 r270 bottom
C31 "Capacitor non-polarized" 0402 61.351,28.987 r270 top
C32 "Capacitor non-polarized" 0402 61.6,21.05 r315 top
C33 "Capacitor non-polarized" 0402 21.1,28.4 r180 bottom
C34 "Capacitor non-polarized" 0402 68.525,24.05 r90 top
C35 "Capacitor non-polarized" 1206 20.6,42.85 r0 top
C36 "Capacitor non-polarized" 0402 68.525,26.55 r270 top
C37 "Capacitor non-polarized" 0805 75.85,23.7 r90 top
C38 "Capacitor non-polarized" 0402 63.271,29.3 r180 top
C39 "Capacitor non-polarized" 0805 8.5,39.55 r0 top
C40 "Capacitor non-polarized" 0402 20.25,35.2 r90 top
C42 "Capacitor non-polarized" 0402 68.525,28.6 r270 top
C43 "Capacitor non-polarized" 0805 32.35,47.458 r90 bottom
C44 "Capacitor non-polarized" 0402 11.9,18.3 r90 top
C45 "Capacitor non-polarized" 0402 51.5,29.825 r180 top
C46 "Capacitor non-polarized" 0402 50.25,26.4 r180 bottom
C47 "Capacitor non-polarized" 0402 50.25,27.5 r180 bottom
C48 "Capacitor non-polarized" 0402 47.05,31.05 r270 bottom
C49 "Capacitor non-polarized" 0805 52,31.05 r180 top
C50 "Capacitor non-polarized" 0402 47.75,24.1 r180 bottom
C51 "Capacitor non-polarized" 0402 44.65,22.8 r270 top
C52 "Capacitor non-polarized" 0402 45.95,31.05 r270 bottom
C53 "Capacitor non-polarized" 0402 43.447,24.79 r0 bottom
C54 "Capacitor non-polarized" 0402 36.05,41.688 r270 top
C55 "Capacitor non-polarized" 0402 41.6,41.8 r90 top
C56 "Capacitor non-polarized" 0402 60.55,34.35 r0 bottom
C57 "Capacitor non-polarized" 0402 52.2,41.1 r270 top
C59 "Capacitor non-polarized" 0805 40.65,32 r270 top
C60 "Capacitor non-polarized" 1210 23.9,5 r0 top
C61 "Capacitor non-polarized" 0402 25.8,8 r90 top
C62 "Capacitor non-polarized" 0402 42.25,31.5 r270 top
C63 "Capacitor non-polarized" 0402 51,29.65 r180 bottom
C64 "Capacitor non-polarized" 0402 51.2,41.1 r270 top
C66 "Capacitor non-polarized" 0402 42.7,41.8 r90 top
C68 "Capacitor non-polarized" 1206 29.4,14.2 r180 top
C69 "Capacitor non-polarized" 1206 29.4,16.5 r180 top
C70 "Capacitor non-polarized" 0402 35.6,6.55 r0 top
C71 "Capacitor non-polarized" 0402 35.05,4.55 r270 top
C72 "Capacitor non-polarized" 0805 18.6,12.5 r0 top
C73 "Capacitor non-polarized" 0805 18.6,10.6 r0 top
C74 "Capacitor non-polarized" 0402 16.08,34.4 r180 top
C75 "Capacitor non-polarized" 0805 50.8,25.005 r180 bottom
C77 "Capacitor non-polarized" 0805 29.65,44.485 r0 bottom
C81 "Capacitor non-polarized" 0805 23.2,22.8 r270 bottom
C83 "Capacitor non-polarized" 0603 26.05,21.1 r180 top
C84 "Capacitor non-polarized" 0603 21.5,15.1 r90 top
C85 "Capacitor non-polarized" 0805 21,15.1 r90 bottom
C86 "Capacitor non-polarized" 0402 25.05,18.75 r0 bottom
C87 "Capacitor non-polarized" 0402 23.9,15.45 r270 bottom
C89 "Capacitor non-polarized" 0603 70.2,24.45 r270 top
C90 "Capacitor non-polarized" 0603 70.15,28.05 r90 top
C91 "Capacitor non-polarized" 0805 51.45,31.05 r180 bottom
C92 "Capacitor non-polarized" 0402 48.833,11.05 r90 top
COL0 "Test Pad" PAD_1mm_SMD#1 50.3,18.5 r0 top
COL1 "Test Pad" PAD_1mm_SMD#1 49.65,19.6 r0 top
COL2 "Test Pad" PAD_1mm_SMD#1 49,18.5 r0 top
COL3 "Test Pad" PAD_1mm_SMD#1 48.35,19.6 r0 top
COL4 "Test Pad" PAD_1mm_SMD#1 47.7,18.5 r0 top
COL5 "Test Pad" PAD_1mm_SMD#1 47.05,19.6 r0 top
COL6 "Test Pad" PAD_1mm_SMD#1 46.4,18.5 r0 top
COL7 "Test Pad" PAD_1mm_SMD#1 45.75,19.6 r0 top
CS "Test Pad" PAD_1mm_SMD#2 70.85,37.65 r90 top
DM+ "Test Pad" PAD_1mm_SMD#1 56.75,10.75 r0 top
DM- "Test Pad" PAD_1mm_SMD#1 55.55,13.15 r0 top
FLUSH "Test Pad" PAD_1mm_SMD#1 56.429,22.902 r180 top
FS "Test Pad" PAD_1mm_SMD#1 37.641,25.759 r0 top
GND1 "Test Pad" PAD_1.27mm_HMD 67.1,0.95 r0 top
GND2 "Test Pad" PAD_1.27mm_HMD 16.6,48.5 r0 top
GPO1 "Test Pad" PAD_1mm_SMD#3 51.975,47.8 r0 top
GPO2 "Test Pad" PAD_1mm_SMD#3 50.425,47.8 r0 top
GPO3 "Test Pad" PAD_1mm_SMD#3 48.907,47.85 r0 top
HS "Test Pad" PAD_1mm_SMD#1 39.05,24.65 r0 top
L1 "Ferrite" 0603 51.4,32.7 r0 bottom
L2 "Inductor" WE-TPC_S 12.65,41.2 r180 top
L3 "Inductor" CC-XAL5050 29.4,10.1 r90 top
L4 "Inductor" WE-TPC_MH 25.8,40.05 r0 top
L6 "Ferrite" 0603 38.35,31.1 r0 top
L7 "Ferrite" 0603 54.9,34.6 r0 bottom
L8 "Ferrite" 0603 52,32.5 r180 top
L9 "Ferrite" 0603 23.5,17.2 r180 bottom
L10 "Ferrite" 0603 23.3,19.5 r270 bottom
L12 "Ferrite" 0603 51.8,23.405 r0 bottom
L14 "Ferrite" 0805 9.8,7.25 r270 top
L15 "Ferrite" 0805 23.2,1.35 r0 top
L17 "Ferrite" 0603 10.15,24.6 r180 bottom
LEN "Test Pad" PAD_1mm_SMD#1 55.1,24.6 r90 top
LH1 "small optic" lensholder_M12_CS_mult 65,25 r0 top locked
LH2 "small optic" lensholder_M12_NLS-2 65,25 r0 top locked
MH1 "Test Pad" PAD_M2-5x5 2.75,2.7 r0 top
MH2 "Test Pad" PAD_M2-5x5 39.55,47.1 r0 top
MH3 "Test Pad" PAD_M2-5x5 77.25,2.7 r0 top
MH4 "Test Pad" PAD_M2-5x5 2.75,47.3 r270 top
MH5 "Test Pad" PAD_M2-5x5 77.25,47.3 r270 top
MH6 "Test Pad" PAD_M2-5x5 39.55,2.9 r90 top locked
nINT "Test Pad" PAD_1mm_SMD#1 26.95,23.1 r0 top
PCB "850-5440" PCB 45,0.9 r0 top
PCLK "Test Pad" PAD_1mm_SMD#1 33.4,18.5 r0 top
Pos1 "Position" Pos-QUADRAT 62,2 r0 top
Pos2 "Position" Pos-QUADRAT 1.9,28.65 r0 top
Pos3 "Position" Pos-QUADRAT 45,47 r0 top
Pos4 "Position" Pos-QUADRAT 3,29 r180 bottom
Pos5 "Position" Pos-QUADRAT 43,8 r180 bottom
Pos6 "Position" Pos-QUADRAT 71,47 r180 bottom
R1 "Resistor" 0402 25.3,14.3 r270 top
R2 "Resistor" 0402 21.5,18.6 r0 bottom
R3 "Resistor" 0603 61.35,32.2 r90 bottom
R4 "Resistor" 0402 13.6,23.4 r0 top
R5 "Resistor" 0402 26.3,15.4 r270 top
R6 "Resistor" 0402 43.45,17.75 r180 top
R7 "Resistor" 0402 34.9,1 r0 top
R8 "Resistor" 0603 39.95,16.3 r270 top
R9 "Resistor" 0402 17.4,42.85 r90 top
R10 "Resistor" 0402 48.833,8.7 r90 top
R11 "Resistor" 0402 49.8,36.45 r270 top
R12 "Resistor" 0402 48.833,36.45 r270 top
R13 "Resistor" 0402 8.65,35.7 r270 top
R14 "Resistor" 0402 38.65,23.439 r180 bottom
R15 "Resistor" 0402 46.1,38.1 r180 top
R16 "Resistor" 0402 5.5,39.85 r0 top
R17 "Resistor" 0603 39.95,18.1 r270 top
R18 "Resistor" 0402 29.9,1 r180 top
R19 "Resistor" 0402 11.294,16.594 r180 top
R20 "Resistor" 0402 6.05,39.3 r90 top
R21 "Resistor" 0402 47.2,37.075 r180 top
R25 "Resistor" 0402 21.8,41 r0 top
R26 "Resistor" 0402 19.55,41 r0 top
R27 "Resistor" 0402 21.2,35.2 r270 top
R28 "Resistor" 0402 30.65,30.95 r270 top
R29 "Resistor" 0402 36.15,4.55 r90 top
R30 "Resistor" 0402 32.6,1 r180 top
R32 "Resistor" 0402 25.4,2.8 r180 top
R33 "Resistor" 0402 36.1,21.65 r90 top
R34 "Resistor" 0402 37.3,22 r90 top
R35 "Resistor" 0402 29.8,31.15 r270 top
R36 "Resistor" 0402 26.5,1.45 r0 top
R37 "Resistor" 0805 30,42.7 r180 bottom
R38 "Resistor" 0805 31.9,42.7 r0 bottom
R41 "Resistor" 0402 25.6,18.7 r180 top
R42 "Resistor" 0402 25.6,19.65 r180 top
R44 "Resistor" 0402 36.4,24.1 r270 top
R45 "Resistor" 0402 35.15,24.1 r270 top
R48 "Resistor" 0402 54.5,10.7 r270 top
R49 "Resistor" 0805 22,45.913 r270 top
R50 "Resistor" 0402 24.7,16.8 r270 top
R51 "Resistor" 0402 22.15,35.2 r270 top
R54 "Resistor" 0402 55.5,11.4 r270 top
R55 "Resistor" 0402 42.35,17.75 r180 top
R56 "Resistor" 0402 51.95,25.05 r90 top
ROW0 "Test Pad" PAD_1mm_SMD#1 52.9,18.6 r0 top
ROW1 "Test Pad" PAD_1mm_SMD#1 51.8,19.25 r0 top
ROW2 "Test Pad" PAD_1mm_SMD#1 52.9,19.9 r0 top
ROW3 "Test Pad" PAD_1mm_SMD#1 51.8,20.55 r0 top
ROW4 "Test Pad" PAD_1mm_SMD#1 52.9,21.2 r0 top
ROW5 "Test Pad" PAD_1mm_SMD#1 51.8,21.85 r0 top
ROW6 "Test Pad" PAD_1mm_SMD#1 52.9,22.5 r0 top
ROW7 "Test Pad" PAD_1mm_SMD#1 51.8,23.15 r0 top
RST "Test Pad" PAD_1mm_SMD#1 54.3,23.7 r90 top
SHUT "Test Pad" PAD_1mm_SMD#1 58.3,21.3 r90 top
U1 "DS90UB925" QFN48-0.5-7-largeEP 20,21.2 r0 top
U2 "XTAL-IC" JO32 38.65,41.388 r0 top
U3 "TPS54061" PSO8-1.27-7.3 30.7,4.4 r0 top
U4 "ADP2108TSOP" TSOT23-5-0.95-2.8 8.25,42.35 r0 top
U5 "TPS62097" VQFN16A4-0.5-3-1 20.95,38.3 r270 top
U6 "MLX75024" COG-N44-MLX75023 65,25 r270 top
U7 "MLX75123xLA-BAG" ELP84-0.5-7-1 46.55,27.6 r90 top locked
U8 "TMP108" BGA6-0.4-0.25-1.2x0.8 67.25,20.45 r180 top
U9 "TMP108" BGA6-0.4-0.25-1.2x0.8 48.842,32.157 r0 top
U10 "PSoC Mixed Signal-Array" TSSOP16-0.65--6.4 43.7,43.7 r0 top
U11 "MCP4725" SOT23-6-0.95--3.3 16.437,32.008 r270 top
U12 "High-Speed LDO Voltage-Regulator" SOT23-5-0.95--3.6 46.433,9.9 r90 top
U13 "MAX828" SOT23-5-0.95--3.6 29.75,47.458 r90 bottom
U14 "PCA9306" VQFN8-0.5-1.6-0.6 10.3,19 r180 top
U15 "SN74LVC1G17" SOT353-0.65--2.6 18,33.75 r180 bottom
U16 "MIC550x" DFN4-0.65-1-0.5 9.15,33.85 r90 top
U17 "TXB0102" VSSOP8-0.5--3.2 21.075,30.95 r270 bottom
V1 "Default Diode" TO-277-3 34.8,10.6 r180 top
V2 "N-MOSFET" SOT23-3-0.95-2.3 40.3,25.7 r180 bottom
V3 "Schottky Diode" SOD523 44.55,23.85 r180 bottom
V4 "P-MOSFET" SOT23-3-0.95-2.3 41.9,22.35 r270 bottom
VMIXH "Test Pad" PAD_1.27mm_HMD 67.05,48.1 r0 top
VS "Test Pad" PAD_1mm_SMD#1 40.85,24.2 r0 top
X1 "CON20(1-2)" SAM-LSS-110-02-F-DV-A 7,25 r270 top locked
X2 "USB_micro_3" USB_micro_3 11,1.55 r0 top
X4 "CON20(1-2)" SAM-LSS-110-02-F-DV-A 15,26 r270 bottom locked

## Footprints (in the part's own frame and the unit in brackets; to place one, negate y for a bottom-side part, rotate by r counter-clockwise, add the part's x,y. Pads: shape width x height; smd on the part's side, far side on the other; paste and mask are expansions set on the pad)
0402 [mm]
  rect 0.6x0.6 smd: 1(-0.55,0) 2(0.55,0)
  silkscreen extent -1,-0.4 1,0.4, body extent -0.51,-0.25 0.51,0.25, height 0.41
0603 [mm]
  rect 0.9x1 smd: 1(-0.9,0) 2(0.9,0)
  silkscreen extent -1.5,-0.6 1.5,0.6, body extent -0.89,-0.38 0.89,0.38, height 0.76
0805 [mm]
  rect 1x1.3 smd: 1(-0.95,0) 2(0.95,0)
  silkscreen extent -1.6,-0.8 1.6,0.8, body extent -1,-0.51 1,0.51, height 1
1206 [mm]
  rect 1.6x1.8 smd: 1(-1.4,0) 2(1.4,0)
  silkscreen extent -2.3,-1 2.3,1, body extent -1.45,-0.76 1.45,0.76, height 1.51
1210 [mm]
  rect 1.6x2.7 smd: 1(-1.4,0) 2(1.4,0)
  silkscreen extent -2.35,-1.45 2.35,1.5, body extent -1.61,-1.26 1.61,1.3, height 2.51
BGA6-0.4-0.25-1.2x0.8 [mm]
  round 0.25 smd: A1(-0.2,0.4) A2(0.2,0.4) B1(-0.2,0) B2(0.2,0) C1(-0.2,-0.4) C2(0.2,-0.4)
  silkscreen extent -0.69,-0.6 0.4,0.96, body extent -0.4,-0.6 0.4,0.6, height 0.63
CC-XAL5050 [mm]
  rect 1.2x4.2 smd: 1(-1.65,0) 2(1.65,0)
  silkscreen extent -2.7,-2.8 2.7,2.8, body extent -2.74,-2.84 2.74,2.84, height 5.1
COG-N44-MLX75023 [mm] "BGA, 256-Leads, Body 9,00x9,00mmx1,20mm, Pitch 0,50mm"
  round 0.7 hole 0.4: 0(-2.074,1.402) 0(-2.074,-1.598) 0(2.206,1.402) 0(2.206,-1.598)
  round 1.2 hole 1: 0(0.066,-0.098)
  round 0.18 smd mask+0.05: 1(-3.135,2) 2(-3.135,1.534) 3(-3.135,1.067) 4(-3.135,0.601) 5(-3.135,0.135) 6(-3.135,-0.331) 7(-3.135,-0.797) 8(-3.135,-1.263) 9(-3.135,-1.729) 10(-3.135,-2.195) 11(-2.583,-2.732) 12(-2.101,-2.732) 13(-1.62,-2.732) 14(-1.138,-2.732) 15(-0.656,-2.732) 16(-0.174,-2.732) 17(0.307,-2.732) 18(0.789,-2.732) 19(1.271,-2.732) 20(1.752,-2.732) 21(2.234,-2.732) 22(2.716,-2.732) 23(3.267,-2.195) 24(3.267,-1.729) 25(3.267,-1.263) 26(3.267,-0.797) 27(3.267,-0.331) 28(3.267,0.135) 29(3.267,0.601) 30(3.267,1.067) 31(3.267,1.534) 32(3.267,2) 33(2.716,2.536) 34(2.234,2.536) 35(1.752,2.536) 36(1.271,2.536) 37(0.789,2.536) 38(0.307,2.536) 39(-0.174,2.536) 40(-0.656,2.536) 41(-1.138,2.536) 42(-1.62,2.536) 43(-2.101,2.536) 44(-2.583,2.536)
  silkscreen extent -3.72,-2.85 3.38,2.65, body extent -3.24,-2.82 3.37,2.65, height 0.75
DFN4-0.65-1-0.5 [mm]
  rect 0.48x0.48 smd rot 45: 0(0,0)
  rect 0.25x0.22 smd: 1(-0.325,-0.54) 2(0.325,-0.54) 3(0.325,0.54) 4(-0.325,0.54)
  Top Layer region: 0.45,0.65 0.45,0.25 0.38,0.25 0.2,0.43 0.2,0.65
  Top Layer region: -0.45,-0.65 -0.45,-0.18 -0.2,-0.43 -0.2,-0.65
  Top Layer region: -0.45,0.65 -0.45,0.25 -0.38,0.25 -0.2,0.43 -0.2,0.65
  Top Layer region: 0.45,-0.65 0.45,-0.25 0.38,-0.25 0.2,-0.43 0.2,-0.65
  silkscreen extent -0.75,-0.65 0.5,0.3, body extent -0.5,-0.5 0.5,0.5, height 0.7
ELKO_SMD-8x7 [mm] "Elko"
  rect 4x1 smd: 1(2.9,0) 2(-2.9,0)
  silkscreen extent -4.15,-4.15 4.6,4.15, body extent -4.5,-4.15 4.5,4.15, height 6.9
ELP84-0.5-7-1 [mm]
  rrect4% 4.4x4.4 smd paste-3 mask+0.025: 0(0,0)
  rrect50% 0.25x0.25 smd mask+0.05: A1(-2.5,-3.275) A2(-2,-3.275) A3(-1.5,-3.275) A4(-1,-3.275) A5(-0.5,-3.275) A6(0,-3.275) A7(0.5,-3.275) A8(1,-3.275) A9(1.5,-3.275) A10(2,-3.275) A11(2.5,-3.275) A12(3.275,-2.5) A13(3.275,-2) A14(3.275,-1.5) A15(3.275,-1) A16(3.275,-0.5) A17(3.275,0) A18(3.275,0.5) A19(3.275,1) A20(3.275,1.5) A21(3.275,2) A22(3.275,2.5) A23(2.5,3.275) A24(2,3.275) A25(1.5,3.275) A26(1,3.275) A27(0.5,3.275) A28(0,3.275) A29(-0.5,3.275) A30(-1,3.275) A31(-1.5,3.275) A32(-2,3.275) A33(-2.5,3.275) A34(-3.275,2.5) A35(-3.275,2) A36(-3.275,1.5) A37(-3.275,1) A38(-3.275,0.5) A39(-3.275,0) A40(-3.275,-0.5) A41(-3.275,-1) A42(-3.275,-1.5) A43(-3.275,-2) A44(-3.275,-2.5) B1(-2.25,-2.775) B2(-1.75,-2.775) B3(-1.25,-2.775) B4(-0.75,-2.775) B5(-0.25,-2.775) B6(0.25,-2.775) B7(0.75,-2.775) B8(1.25,-2.775) B9(1.75,-2.775) B10(2.25,-2.775) B11(2.775,-2.25) B12(2.775,-1.75) B13(2.775,-1.25) B14(2.775,-0.75) B15(2.775,-0.25) B16(2.775,0.25) B17(2.775,0.75) B18(2.775,1.25) B19(2.775,1.75) B20(2.775,2.25) B21(2.25,2.775) B22(1.75,2.775) B23(1.25,2.775) B24(0.75,2.775) B25(0.25,2.775) B26(-0.25,2.775) B27(-0.75,2.775) B28(-1.25,2.775) B29(-1.75,2.775) B30(-2.25,2.775) B31(-2.775,2.25) B32(-2.775,1.75) B33(-2.775,1.25) B34(-2.775,0.75) B35(-2.775,0.25) B36(-2.775,-0.25) B37(-2.775,-0.75) B38(-2.775,-1.25) B39(-2.775,-1.75) B40(-2.775,-2.25)
  silkscreen extent -3.5,-3.5 3.5,3.5, body extent -3.5,-3.5 3.5,3.5, height 0.9
JO32 [mm]
  rect 1.3x1.1 smd: 1(-1.15,-0.95) 2(1.15,-0.95) 3(1.15,0.95) 4(-1.15,0.95)
  silkscreen extent -2.35,-1.25 1.6,1.25, body extent -1.6,-1.25 1.6,1.25, height 0.7
lensholder_M12_CS_mult [mm]
  oval 2x4 / inner oval 2x4 / far side oval 4.5x6.5 hole 2 slot 4 at 90 deg unplated: 4(0,-10) 8(0,10)
  body extent -11.5,-12.5 11.5,12.5, height 0.1
lensholder_M12_NLS-2 [mm]
  round 0.6 hole 0.6 unplated: PS1(-8.25,8.25) PS2(8.25,-8.25)
  silkscreen extent -9,-11 9,11, body extent -9,-11 9,11, height 3.73
PAD_1.27mm_HMD [mm]
  round 1.2 hole 0.6 paste-1.5: 1(0,0)
PAD_1mm_SMD#1 [mm]
  round 1 smd paste-1: 1(0,0)
PAD_1mm_SMD#2 [mm]
  round 1 hole 0.6 paste-1: 1(0,0)
PAD_1mm_SMD#3 [mm]
  round 1 hole 0.5 paste-1: 1(0,0)
PAD_M2-5x5 [mm]
  round 5 hole 2.4 paste-1.5: 1(0,0)
  body extent -1.9,-1.9 1.9,1.9, height 2
PCB [mm]
  silkscreen extent -0.35,-0.33 8.13,1.45
Pos-QUADRAT [mm] "Positioning mark cross"
  Top Layer region: -0.5,-0.5 0.5,-0.5 0.5,0.5 -0.5,0.5
  Top Layer keep-out lines w0: -1.5,-1.5 -1.5,1.5 1.5,1.5 1.5,-1.5 -1.5,-1.5
PSO8-1.27-7.3 [mm]
  rect 2.41x3.1 smd paste-3 mask-3: 0(0,0)
  rect 1.9x0.6 smd: 1(-2.78,1.905)
  oval 1.9x0.6 smd: 2(-2.78,0.635) 3(-2.78,-0.635) 4(-2.78,-1.905) 5(2.78,-1.905) 6(2.78,-0.635) 7(2.78,0.635) 8(2.78,1.905)
  silkscreen extent -1.95,-2.45 1.95,2.45, body extent -1.95,-2.45 1.95,2.45, height 1.7
QFN48-0.5-7-largeEP [mm] "QFN, 48-Leads, Body 7,2x7,2mm (max), Pitch 0,50mm, IPC High Density"
  rect 5.1x5.1 smd paste-3: 0(0,0)
  rect 0.65x0.25 smd: 1(-3.525,2.75)
  oval 0.65x0.25 smd: 2(-3.525,2.25) 3(-3.525,1.75) 4(-3.525,1.25) 5(-3.525,0.75) 6(-3.525,0.25) 7(-3.525,-0.25) 8(-3.525,-0.75) 9(-3.525,-1.25) 10(-3.525,-1.75) 11(-3.525,-2.25) 12(-3.525,-2.75) 25(3.525,-2.75) 26(3.525,-2.25) 27(3.525,-1.75) 28(3.525,-1.25) 29(3.525,-0.75) 30(3.525,-0.25) 31(3.525,0.25) 32(3.525,0.75) 33(3.525,1.25) 34(3.525,1.75) 35(3.525,2.25) 36(3.525,2.75)
  oval 0.25x0.65 smd: 13(-2.75,-3.525) 14(-2.25,-3.525) 15(-1.75,-3.525) 16(-1.25,-3.525) 17(-0.75,-3.525) 18(-0.25,-3.525) 19(0.25,-3.525) 20(0.75,-3.525) 21(1.25,-3.525) 22(1.75,-3.525) 23(2.25,-3.525) 24(2.75,-3.525) 37(2.75,3.525) 38(2.25,3.525) 39(1.75,3.525) 40(1.25,3.525) 41(0.75,3.525) 42(0.25,3.525) 43(-0.25,3.525) 44(-0.75,3.525) 45(-1.25,3.525) 46(-1.75,3.525) 47(-2.25,3.525) 48(-2.75,3.525)
  silkscreen extent -4.15,-3.5 3.5,3.55, body extent -3.5,-3.5 3.5,3.5, height 0.85
SAM-LSS-110-02-F-DV-A [mm] "SAM-LSS-105-01-F-DV-A"
  rect 0.4x1.6 smd: 1(2.858,-1.8) 2(2.857,1.8) 3(2.223,-1.8) 4(2.222,1.8) 5(1.588,-1.8) 6(1.587,1.8) 7(0.953,-1.8) 8(0.952,1.8) 9(0.318,-1.8) 10(0.317,1.8) 11(-0.317,-1.8) 12(-0.318,1.8) 13(-0.952,-1.8) 14(-0.953,1.8) 15(-1.587,-1.8) 16(-1.588,1.8) 17(-2.222,-1.8) 18(-2.223,1.8) 19(-2.857,-1.8) 20(-2.858,1.8)
  round 0.8 hole 0.8 unplated: A1(3.925,1.1) A2(-3.925,1.1)
  silkscreen extent -5.59,-2 5.59,2, body extent -5.57,-2.3 5.53,2.3, height 7.45
SOD523 [mm]
  rect 0.75x0.55 smd: 1(0.7,0) 2(-0.7,0)
  silkscreen extent -0.65,-0.4 0.65,0.4, body extent -0.8,-0.4 0.8,0.4, height 0.6
SOT23-3-0.95-2.3 [mm]
  rect 0.9x0.65 smd: 1(-1.1,0.95) 2(-1.1,-0.95) 3(1.1,0)
  silkscreen extent -0.54,-1.5 0.51,1.5, body extent -1.24,-1.46 1.24,1.46, height 1.01
SOT23-5-0.95--3.6 [mm]
  rect 1x0.7 smd: 1(-1.3,0.95) 2(-1.3,0) 3(-1.3,-0.95) 4(1.3,-0.95) 5(1.3,0.95)
  silkscreen extent -0.67,-1.59 0.66,1.46, body extent -1.45,-1.45 1.35,1.45, height 1.09
SOT23-6-0.95--3.3 [mm]
  rect 0.8x0.6 smd: 1(-1.25,0.95) 2(-1.25,0) 3(-1.25,-0.95) 4(1.25,-0.95) 5(1.25,0) 6(1.25,0.95)
  silkscreen extent -0.65,-1.45 0.65,1.45, body extent -1.21,-1.4 1.21,1.39, height 1.09
SOT353-0.65--2.6 [mm]
  rect 0.6x0.4 smd: 1(-1,0.65) 2(-1,0) 3(-1,-0.65) 4(1,-0.65) 5(1,0.65)
  silkscreen extent -0.5,-0.95 0.5,0.95, body extent -1.1,-0.95 1.1,0.95, height 0.95
TO-277-3 [mm] "TO-277-3 / PowerDI"
  rect 1.45x1.15 smd: 1(-0.92,-2.75) 3(0.92,-2.75)
  rect 4.15x4.65 smd: 2(0,1)
  silkscreen extent -2.3,-3.05 2.3,3.05, body extent -2.03,-3.3 2.02,3.3, height 1.17
TSOT23-5-0.95-2.8 [mm]
  rect 0.9x0.6 smd: 1(-1.4,0.95) 2(-1.4,0) 3(-1.4,-0.95) 4(1.4,-0.95) 5(1.4,0.95)
  silkscreen extent -0.8,-1.45 0.8,1.45, body extent -1.65,-1.5 1.55,1.4, height 0.94
TSSOP16-0.65--6.4 [mm]
  rect 1.2x0.3 smd: 1(0.25,0) 2(0.25,-0.65) 3(0.25,-1.3) 4(0.25,-1.95) 5(0.25,-2.6) 6(0.25,-3.25) 7(0.25,-3.9) 8(0.25,-4.55) 9(6.25,-4.55) 10(6.25,-3.9) 11(6.25,-3.25) 12(6.25,-2.6) 13(6.25,-1.95) 14(6.25,-1.3) 15(6.25,-0.65) 16(6.25,0)
  silkscreen extent 1.03,-4.88 5.47,0.33, body extent 1.03,-4.88 5.47,0.33, height 1.21
USB_micro_3 [mm]
  rect 0.4x1.4 smd: 1(-1.3,2.7) 2(-0.65,2.7) 3(0,2.7) 4(0.65,2.7) 5(1.3,2.7) 6(5.4,2.7) 7(6.05,2.7) 8(6.7,2.7) 9(7.35,2.7) 10(8,2.7)
  rect 2.3x1.9 smd: 11(9.1,0)
  rect 1.9x1.9 smd: 12(6.5,0) 13(4,0) 14(1.2,0) 15(-1.2,0) 16(-3.6,0)
  silkscreen extent -4.05,-2.75 9.75,2.95, body extent -4.03,-2.75 9.78,2.95, height 2.77
VQFN8-0.5-1.6-0.6 [mm]
  rect 0.55x0.25 smd paste-0.03: 1(-0.6,0.5) 2(-0.6,0) 3(-0.6,-0.5) 5(0.6,-0.5) 6(0.6,0) 7(0.6,0.5)
  rect 0.25x0.55 smd paste-0.03: 4(0,-0.6) 8(0,0.6)
  silkscreen extent -0.8,-0.8 0.8,1.3, body extent -0.8,-0.8 0.8,0.8, height 12
VQFN16A4-0.5-3-1 [mm]
  rrect10% 1.68x1.68 smd paste-0.065: 0(0,0)
  rrect50% 0.6x0.25 smd: 1(-1.4,0.75) 2(-1.4,0.25) 3(-1.4,-0.25) 4(-1.4,-0.75) 9(1.4,-0.75) 10(1.4,-0.25) 11(1.4,0.25) 12(1.4,0.75)
  rrect50% 0.25x0.6 smd: 5(-0.75,-1.4) 6(-0.25,-1.4) 7(0.25,-1.4) 8(0.75,-1.4) 13(0.75,1.4) 14(0.25,1.4) 15(-0.25,1.4) 16(-0.75,1.4)
  rrect50% 0.6x0.2 smd: A1(-1.4,1.2) A2(-1.4,-1.2) A3(1.4,-1.2) A4(1.4,1.2)
  rrect50% 0.2x0.6 smd: A1(-1.2,1.4) A2(-1.2,-1.4) A3(1.2,-1.4) A4(1.2,1.4)
  silkscreen extent -1.8,-1.5 1.5,1.8, body extent -1.5,-1.5 1.5,1.5, height 1
VSSOP8-0.5--3.2 [mm]
  rect 0.7x0.25 smd: 1(-1.6,0.75)
  oval 0.7x0.25 smd: 2(-1.6,0.25) 3(-1.6,-0.25) 4(-1.6,-0.75) 5(1.6,-0.75) 6(1.6,-0.25) 7(1.6,0.25) 8(1.6,0.75)
  silkscreen extent -1.1,-1.15 1.1,1.15, body extent -1.8,-1.15 1.8,1.15, height 0.91
WE-TPC_MH [mm]
  rect 5.3x2 smd: 1(0,-1.75) 2(0,1.75)
  silkscreen extent -2.5,-0.6 2.5,0.6, body extent -2.4,-2.4 2.4,2.4, height 2.79
WE-TPC_S [mm]
  rect 4.5x1.6 smd: 1(0,-1.35) 2(0,1.35)
  silkscreen extent -1.9,-1.9 1.9,1.9, body extent -1.91,-1.91 1.91,1.91, height 1.7

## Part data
1V8 3V3 3V3A ABIAS GND1 GND2 VMIXH: library part 27F6ED3A-68E1-4461-ACCB-196987D0D511, "Test Pad 1.27mm", Manufacturer=Bluetechnix, Supplier Part Number 1=------
1V8A 1V8ADC 1V8ADCS 1V8D 3V3CC COL0 COL1 COL2 COL3 COL4 COL5 COL6 COL7 CS DM+ DM- FLUSH FS GPO1 GPO2 GPO3 HS LEN nINT PCLK ROW0 ROW1 ROW2 ROW3 ROW4 ROW5 ROW6 ROW7 RST SHUT VS: library part D58E77CC-74E0-4972-9B60-0D1F1EE06ED8, "Test Pad 1mm", Manufacturer=Bluetechnix, Supplier Part Number 1=-----
C1 C2 C4 C6 C9 C11 C15 C24 C31 C32 C33 C34 C36 C42 C44 C45 C46 C47 C48 C50 C51 C52 C53 C54 C56 C61 C62 C63 C64 C66 C74 C86 C87 C92: library part 54C877D5-E705-4C14-AD3D-8F4F7B57D597, "C-0402-100n-16V-10%", Manufacturer=Murata, Supplier Part Number 1=8819742, Toleranz=10%
C3 C5 C7 C16 C18 C22 C89 C90: library part E75EC942-B97D-4F35-9B30-0E69ABA45798, "C-0603-4u7-6.3V-10%", Manufacturer=Kemet, Supplier Part Number 1=9227784, Toleranz=10%
C8 C27 C72 C73: library part 673ACA82-F2DF-4178-940F-1238A813E141, "C-0805-100n-50V-10%", Manufacturer=AVX, Supplier Part Number 1=7569564, Toleranz=10%
C10 C19 C25 C26 C77: library part 81c3c59d-90b6-45b0-bf00-0272af6cd427, "C-0805-1u-16V-10%", Manufacturer=KEMET, Supplier Part Number 1=9227792, Toleranz=10%
C12 C29 C30 C37 C49 C59 C75 C91: library part D0FA8253-90B1-4ECC-BCBB-ABE84B083618, "C-0805-10u-6.3V-X7R", Manufacturer=Murata, Supplier Part Number 1=2320851, Toleranz=10%
C13 C60: library part c11633e3-883f-4ea1-bab5-305a930c1712, "C-1210-2u2-100V-X7R", Manufacturer=Kemet, Supplier Part Number 1=1793832, Toleranz=10%
C14 C20 C28 C39 C43: library part cf916b3d-c256-4339-9e5e-93049cd4a086, "C-0805-10u-6.3V-10%", Manufacturer=AVX, Supplier Part Number 1=581-08056C106KAT2A, Toleranz=10%
C17: library part 44276342-0de9-47a7-a7a6-11334c4a2d95, "C-39u-35V-20%-30mR", Manufacturer=Panasonic, Supplier Part Number 1=2354808, Toleranz=20%
C21 C81 C85: library part 9F754684-D939-469A-B40A-D1B375B83304, "C-0805-22u-6.3V-20%", Manufacturer=AVX, Supplier Part Number 1=478-3647-1-ND, Toleranz=20%
C23: library part 85fb7b5b-9611-43b8-8d58-2b78e382f91e, "C-1206-100u-6.3V-20%-X6T", Manufacturer=Murata, Supplier Part Number 1=885-1897, Toleranz=20%
C35 C68 C69: library part f3686e78-9391-4e70-aeac-48820653bfbe, "C-1206-22u-16V-10%-X6S", Manufacturer=Murata, Supplier Part Number 1=1889296, Toleranz=20%
C38: library part 98DACC71-806A-4FEE-A07A-D9A6BAB2B1B9, "C-0402-1u-6.3V-20%", Manufacturer="Taiyo Yuden", Supplier Part Number 1=81-GRM155R70J105MA2D, Toleranz=20%
C40: library part F3AE35C4-38BD-40F1-9F89-DFB06C81C85C, "C-0402-10n-25V-10%", Manufacturer=Murata, Supplier Part Number 1=8819734, Toleranz=10%
C55 C57: library part ec10d741-eb09-41f2-b621-026af504b23c, "C-0402-100p-50V-5%", Manufacturer=Samsung, Toleranz=5%
C70: library part 1E20E73B-F110-4E82-8339-165F61C8EA2C, "C-0402-56n-16V-10%", Manufacturer=KEMET, Supplier Part Number 1=399-4901-1-ND, Toleranz=10%
C71: library part D729ACC2-10DA-4FA5-B88D-D769CEA10CA7, "C-0402-47p-50V-5%", Manufacturer=AVX, Supplier Part Number 1=1327639, Toleranz=5%
C83 C84: library part 7C0C21CA-74A8-454E-BED5-E74A03E0EDB6, "C-0603-10n-25V-5%", Manufacturer=Kemet, Supplier Part Number 1=1457729, Toleranz=5%
L1 L6 L7 L8 L12: library part 07176BF7-A3FD-44A1-A821-88F0A6433C5F, "F-0603-220Z-500mA", Frequenz=400MHz, Manufacturer="Würth Elektronik", Supplier Part Number 1=_4000038
L2: library part AA01E2E0-360B-48B6-A8ED-1CE20DAAC179, "L-WE-TPC-S-1u5-1.75A-30%", Manufacturer="Würth Elektronik", Supplier Part Number 1=1635833, Toleranz=30%
L3: library part ebdded0c-8af9-41bf-8a12-8fcfe7c8f423, "L-XAL5050-10u-4.9A-20%", Manufacturer=Coilcraft, Supplier Part Number 1=994-XAL5050-103MEB, Toleranz=20%
L4: library part 8BFA9BBF-0541-4A3A-9EC6-D13966CA382E, "L-WE-TPC-MH-1u2-3.1A", Manufacturer="Würth Elektronik", Supplier Part Number 1=7440430012, Toleranz=30%
L9 L10: library part EB1B1D42-458D-46E7-BD46-C9CB50225E79, "F-0603-1000Z-500mA", Frequenz=900MHz, Manufacturer="Taiyo Yuden", Supplier Part Number 1=587-1739-1-ND
L14 L15: library part 4558f3ef-a2ca-4732-a97e-33e36c5aad12, "F-0805-120Z-5A", Frequenz=300MHz, Manufacturer="MEC MARCOM", Supplier Part Number 1=1308778
L17: library part b9289626-3563-4556-94c6-b2bf7f242055, "F-0603-1000Z-100mA", Frequenz=200MHz, Manufacturer=Murata, Supplier Part Number 1=1515701
LH1: library part fb9d6639-ec39-4f27-9db3-01e0c5ccb563, "Lense Holder M12, CS, multiple", Manufacturer=Unbranded
LH2: library part 6a91d241-ddc7-433f-aaf5-84eaeffba76b, "Lens Holder for M12 lense 3.75mm high", Manufacturer=Naotech
MH1 MH2 MH3 MH4 MH5 MH6: library part d95d2f47-965b-47b2-ac00-e8d5b9325de3, "M2 Mounting Hole 5x5", Manufacturer=Bluetechnix
PCB: library part aa2248c4-82a7-44fd-bdc5-6c4486715852, "PCB_EVK75123-MLX75024 V1.4", Manufacturer=Bluetechnix
Pos1 Pos2 Pos3 Pos4 Pos5 Pos6: library part A97550DC-E5EA-465D-9168-34E3565B8720, "Pos-QUADRAT-3mm", Manufacturer=Bluetechnix, Supplier Part Number 1=-
R1 R7: library part 07979F3D-4677-465C-93AF-4C0DB5A9740C, "R-0402-52k3-1%", Manufacturer=Multicomp, Supplier Part Number 1=1803722, Toleranz=1%
R2 R4 R6 R10 R13 R14 R16 R20 R27 R30 R36 R48 R51 R54 R55 R56: library part BCCEBF77-39D2-4523-BB97-913D11062098, "R-0402-10k-1%", Manufacturer=YAGEO, Supplier Part Number 1=9239359, Toleranz=1%
R3 R8 R17: library part A3495A76-5718-4BF3-84D0-31FEB97D37C9, "R-0603-330R-1%", Manufacturer=Multicomp, Supplier Part Number 1=9331018, Toleranz=1%
R5 R33 R34: library part 5AE00D73-A272-4484-A2BE-57AC9ABCA7A7, "R-0402-15k-1%", Manufacturer=YAGEO, Supplier Part Number 1=9239375, Toleranz=1%
R9: library part 67127F43-32FE-42C1-8D78-F67E7CEF1B7C, "R-0402-39k-1%", Manufacturer=YAGEO, Supplier Part Number 1=9239421, Toleranz=1%
R11 R12: library part BC2B87D0-B6C1-44F9-904C-ACAF31BEC71E, "R-0402-2k-1%", Manufacturer=MULTICOMP, Supplier Part Number 1=1358050, Toleranz=1%
R15: library part 9730678D-3891-499B-9B01-A89CC85559C4, "R-0402-1k5-1%", Manufacturer=YAGEO, Supplier Part Number 1=9239251, Toleranz=1%
R18: library part 36816F37-1497-45EC-A648-00BA6DD1BED6, "R-0402-300k-1%", Manufacturer=PhyComp, Supplier Part Number 1=1458779, Toleranz=1%
R19: library part EB4C6C81-BAA5-401A-97FC-7C0F95811618, "R-0402-200k-1%", Manufacturer=YAGEO, Supplier Part Number 1=1458761, Toleranz=1%
R21: library part 1021EC43-D7C6-4E9F-B4E5-559CA0DA3C67, "R-0402-1k8-1%", Manufacturer=YAGEO, Supplier Part Number 1=9239260, Toleranz=1%
R25: library part 0f3e9f1d-d298-49d2-b2be-77c58d20251a, "R-0402-18k2-1%", Manufacturer=Multicomp, Supplier Part Number 1=2072717, Toleranz=1%
R26: library part 76176D2D-1863-4245-B5AD-CF9DCC6B9442, "R-0402-11k-1%", Manufacturer=Vishay, Supplier Part Number 1=1469673, Toleranz=1%
R28 R29 R35: library part 83EC2591-E07F-42F5-A99F-8FBBFCE4BDFC, "R-0402-5k6-5%", Manufacturer=YAGEO, Supplier Part Number 1=9232850, Toleranz=5%
R32: library part 3de2694c-57ce-4287-83c5-ae949e3a1a26, "R-0402-160k-1%", Manufacturer="VISHAY DRALORIC", Supplier Part Number 1=2140947, Toleranz=1%
R37 R38 R49: library part 96878DCE-2E24-48BD-A958-A9B2669E8EA5, "R-0805-0R-5%", Manufacturer=YAGEO, Supplier Part Number 1=1117368, Toleranz=5%
R41 R42 R44 R45: library part B17B00F1-DBD0-472B-A8A9-768E0D7D14BD, "R-0402-47R-5%", Manufacturer=YAEGO, Supplier Part Number 1=9232605, Toleranz=5%
R50: library part 366df4e7-ff92-4215-b9a2-968f2cab22c9, "R-0402-0R1-1%", Manufacturer=PhyComp, Supplier Part Number 1=1284586, Toleranz=1%
U1: library part 1691325b-6bd3-4e9e-84e0-1aaa7d8a455c, "DS90UB925Q-Q1 5 to 85 MHz 24-Bit Color FPD-Link III Serializer", Manufacturer=TI, Supplier Part Number 1=296-38937-1-ND
U2: library part 00cff2d6-5d29-4f0c-95fc-66dce918587e, "OSC-JO32-20MHz", Frequenz=20MHz, Manufacturer=Microchip, Supplier Part Number 1=DSC1001CL1-020.0000-ND, Toleranz=±50ppm
U3: library part 83e8cd34-1e26-4937-9357-3a852f02699a, "4.5 V to 60 V Input, 5 A, Step Down DC-DC Converter with Eco-mode", Frequenz="100kHz : 2.5MHz", Manufacturer="Texas Instruments", Supplier Part Number 1=595-TPS54560DDAR
U4: library part 1d5217f7-f1b1-4eac-83a6-f563bfe7f909, "3.3V Fixed, 600 mA, 3 MHz, Step-Down DC-to-DC Converter", Frequenz=3MHz, Manufacturer="Analog Devices", Supplier Part Number 1=ADP2108AUJZ-3.3-R7CT-ND
U5: library part d6bf69c1-61e1-4892-bc66-3b908696a342, "High Efficiency single inductor buck/boost 2A", Frequenz="1.5MHz : 2.5 MHz", Manufacturer="Texas Instruments", Supplier Part Number 1=595-TPS62097QWRGTRQ1
U6: library part 2041fcf8-dfaf-4804-8ae0-af23c2aad8e4, "QVGA 3D ToF Sensor", Manufacturer=Melexis
U7: library part 18af0085-4cb3-4911-96c3-c6148f48ab61, "ToF Companion Chip for MLX7502x Rev.B", Manufacturer=Melexis
U8 U9: library part 1756c951-2cf8-4c64-a988-e546f59afa21, "±1°C Accurate 12bit Digital Temperature Sensor", Manufacturer="Texas Instruments", Supplier Part Number 1=2496408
